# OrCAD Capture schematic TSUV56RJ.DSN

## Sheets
1 02. TSUMV56RJXX: size Custom; title: TSUMV56RJ; rev: V1.0; note: TSUMV56RJ
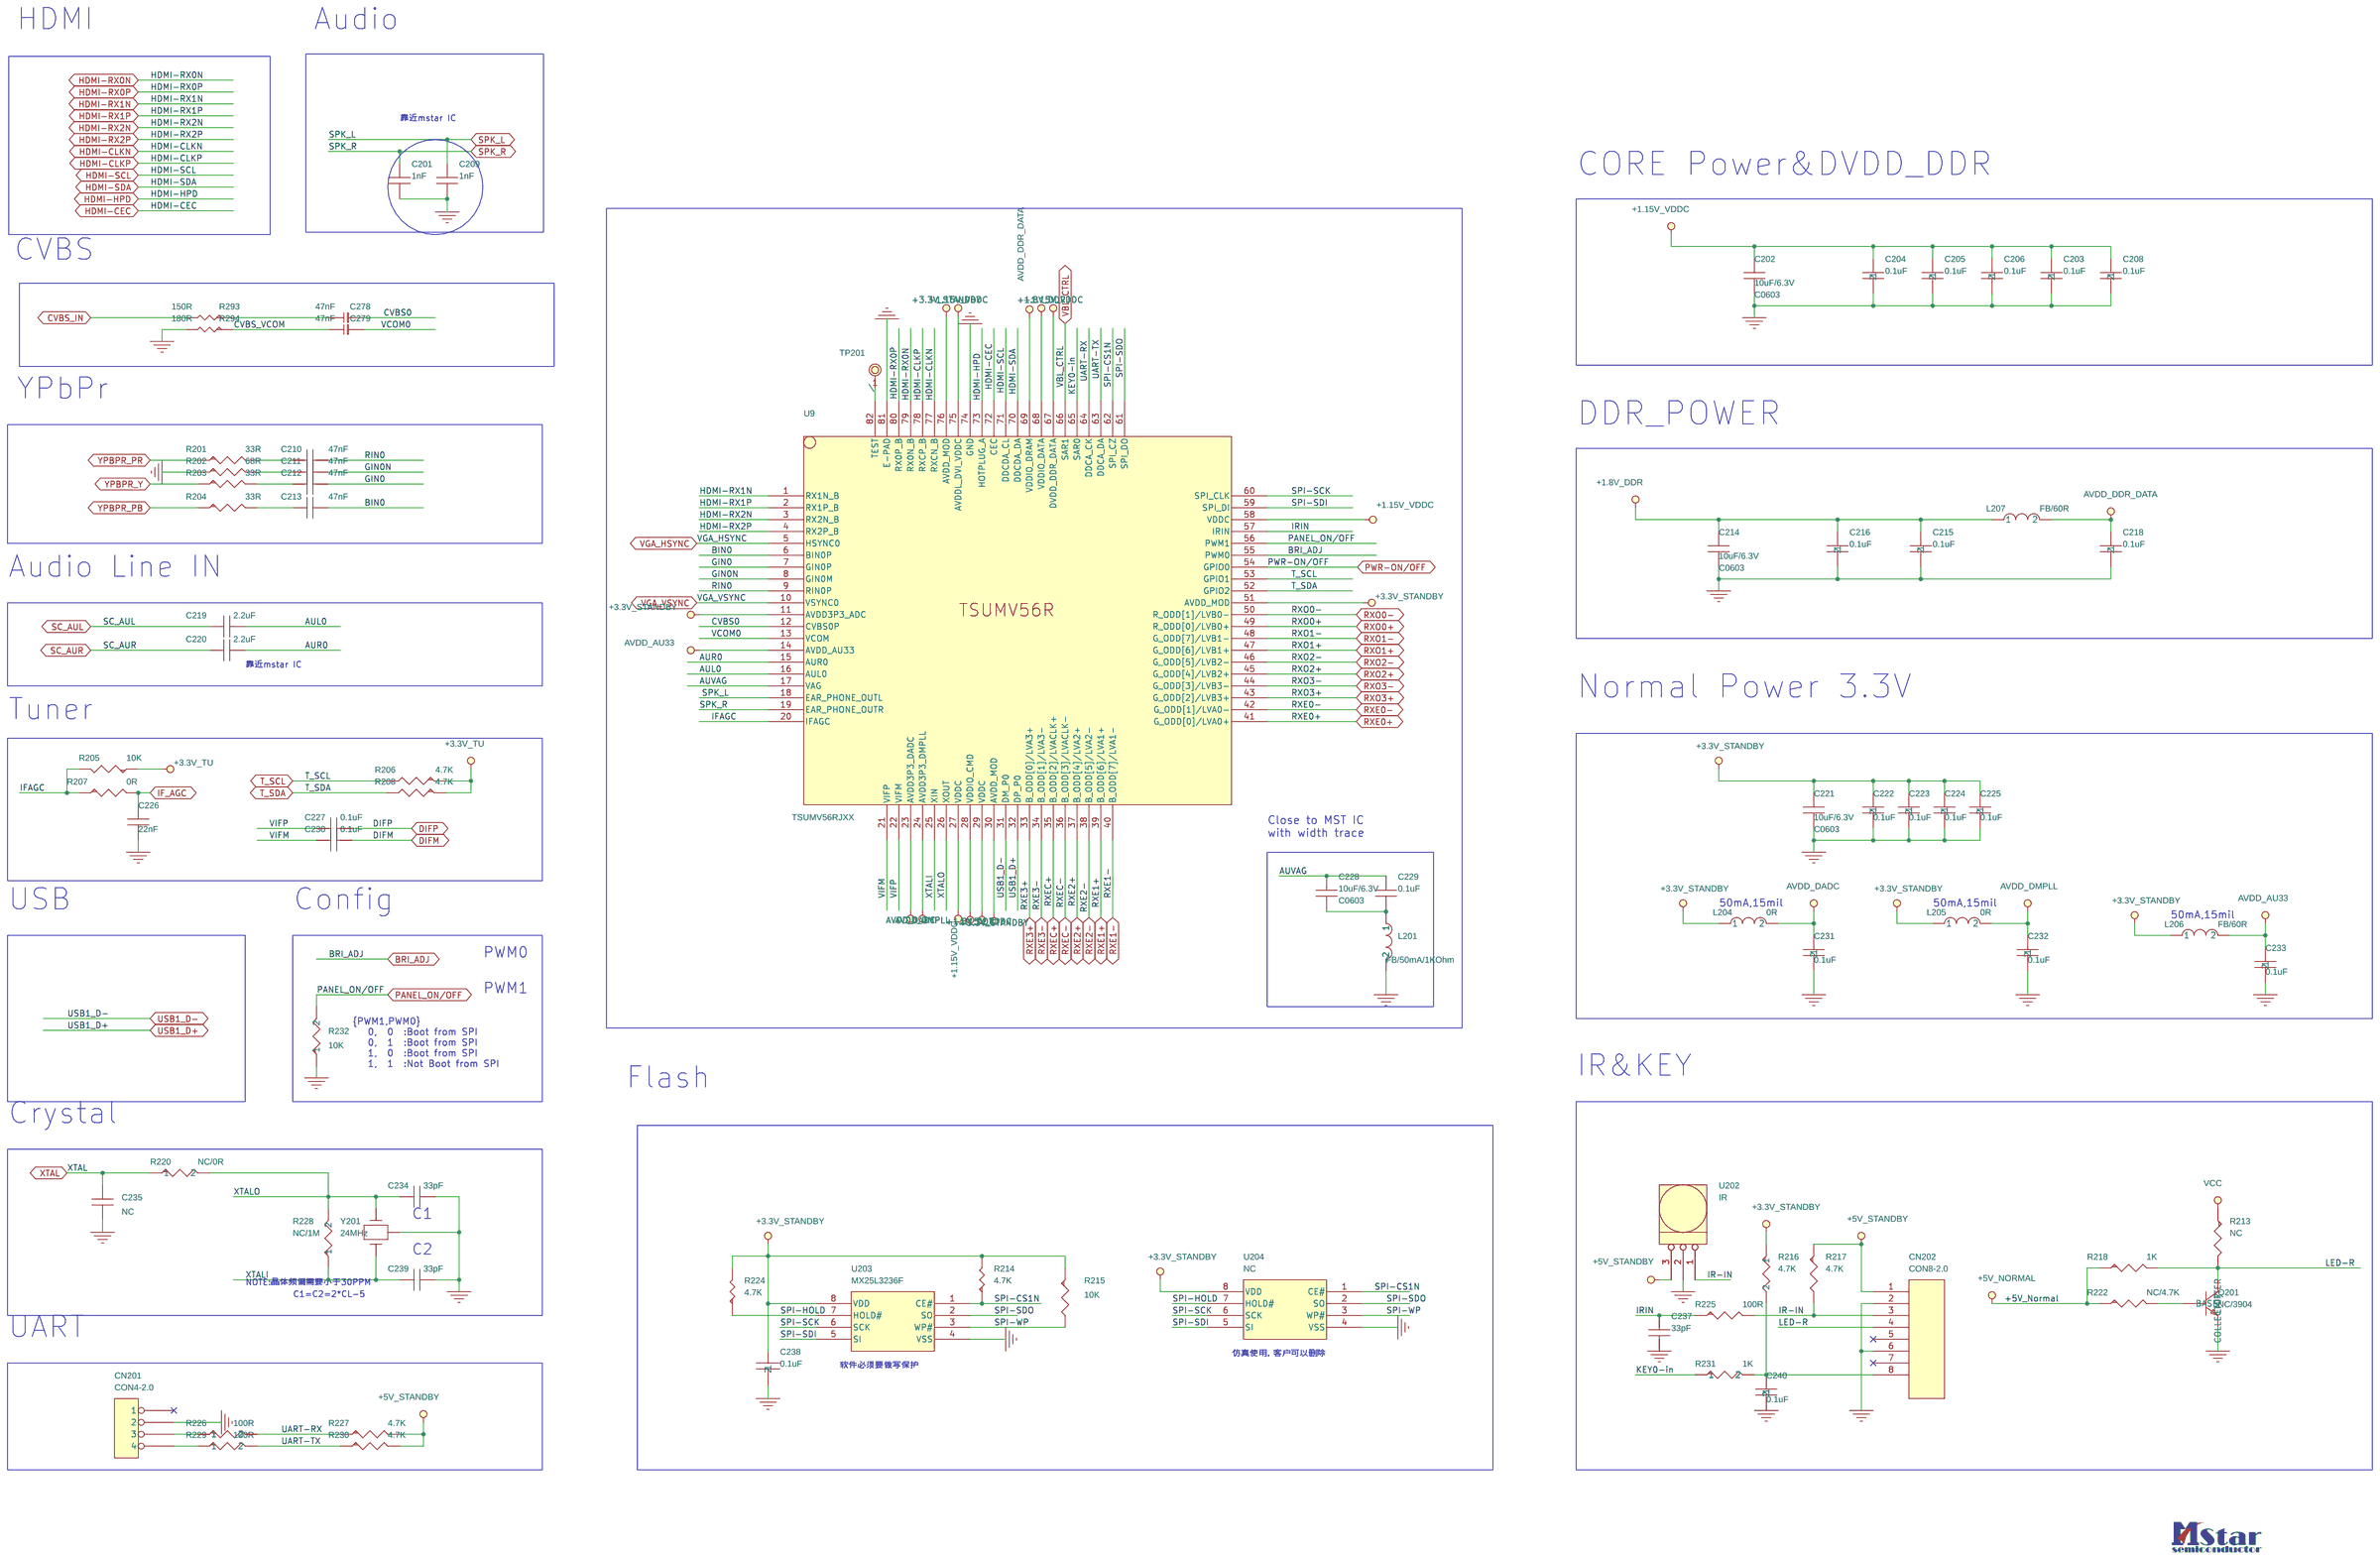
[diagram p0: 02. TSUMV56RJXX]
2 05. Tuner: size Custom; note: Tuner
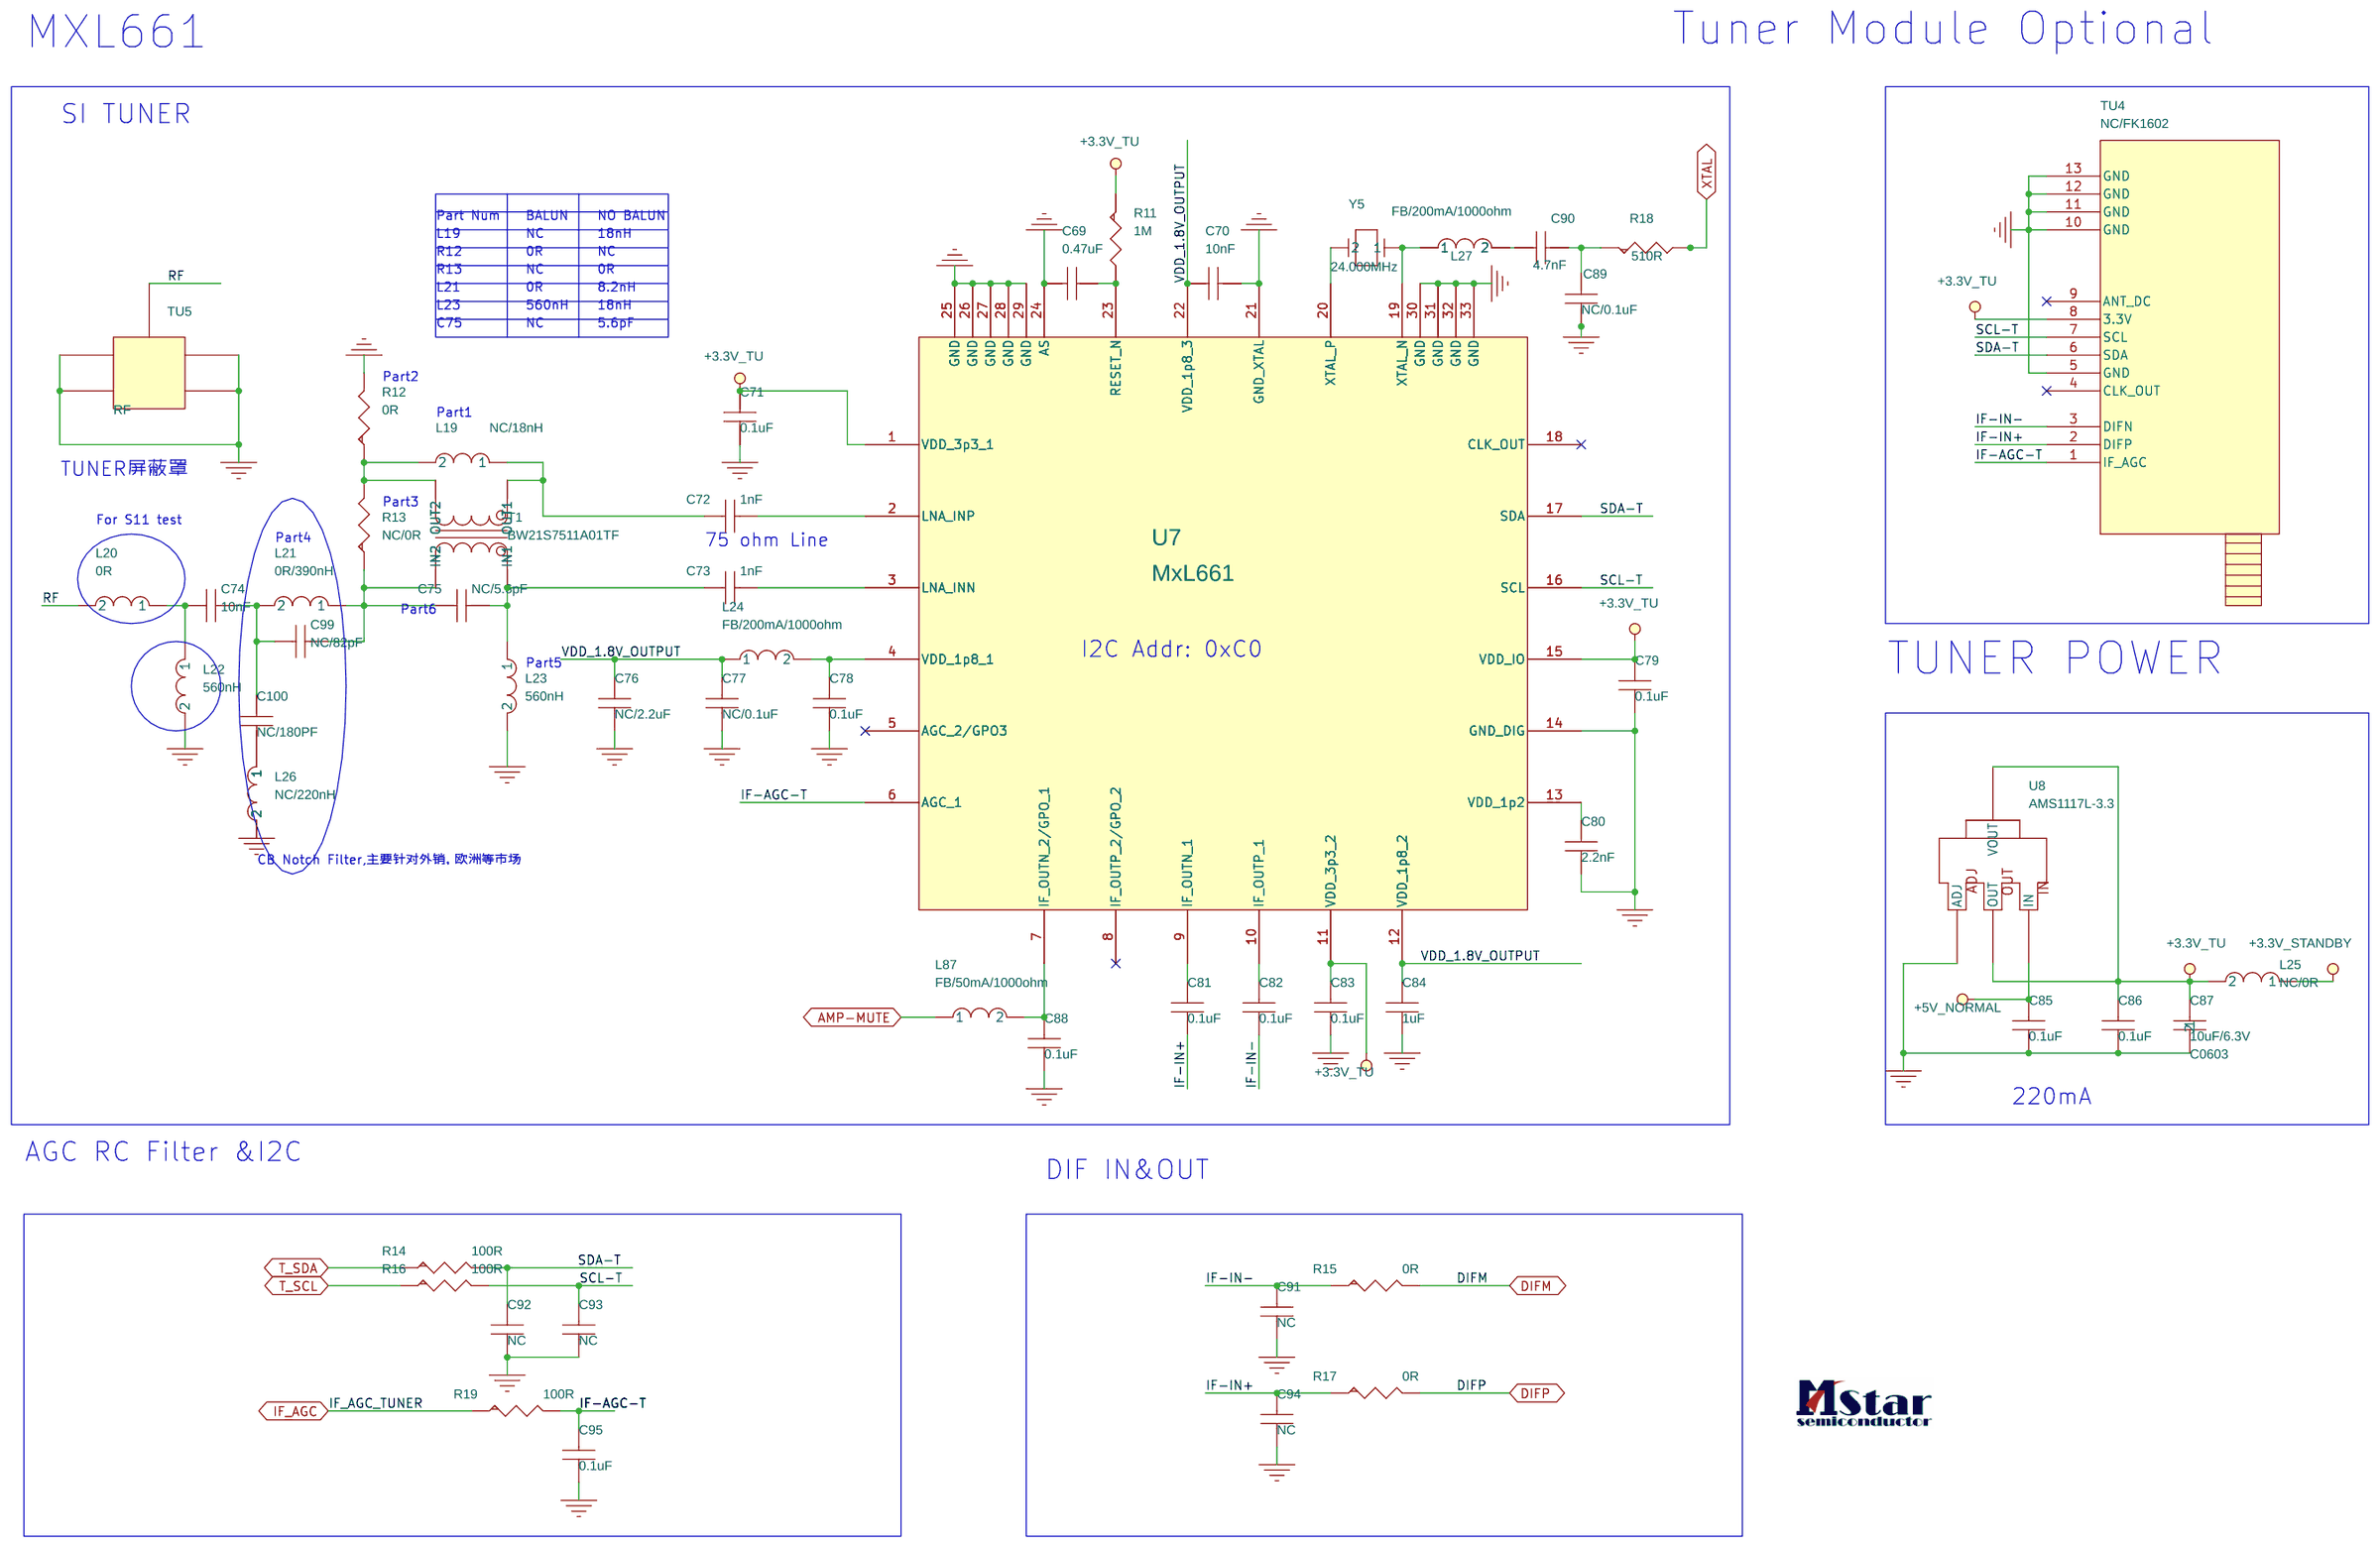
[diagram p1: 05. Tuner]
3 01. System power: size Custom; note: System power
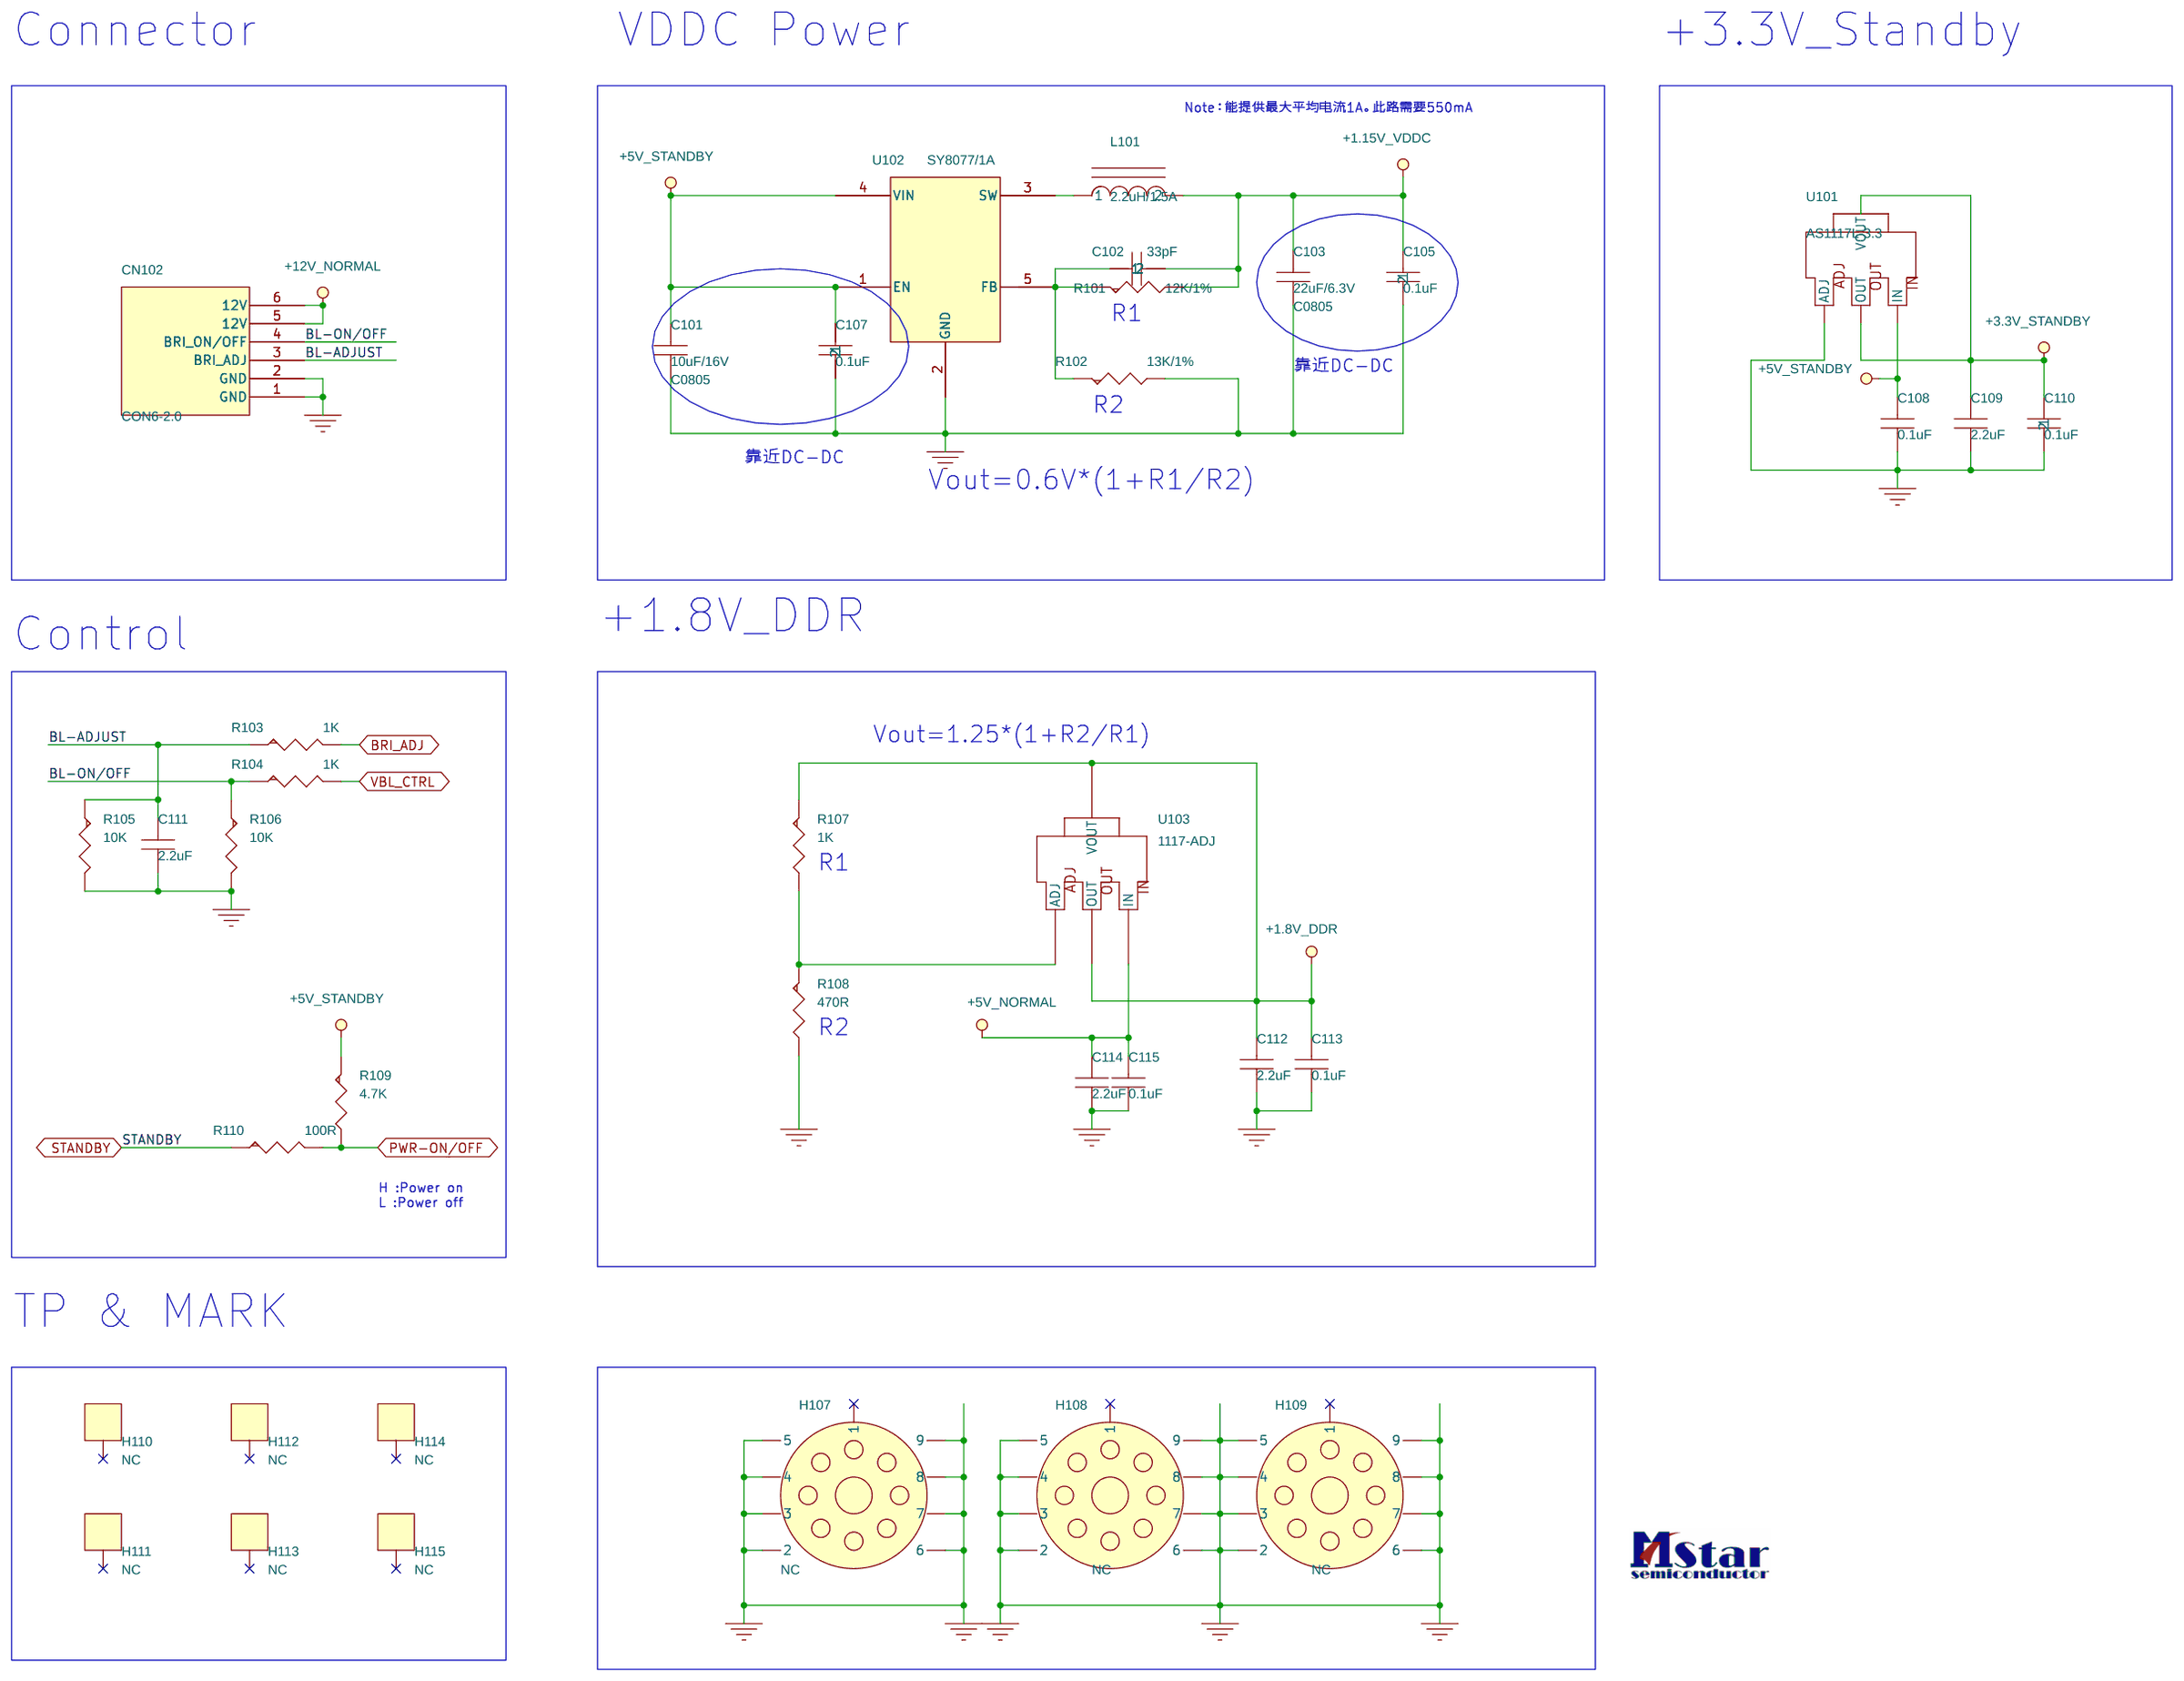
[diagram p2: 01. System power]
4 07. External power board: size Custom; note: External power board
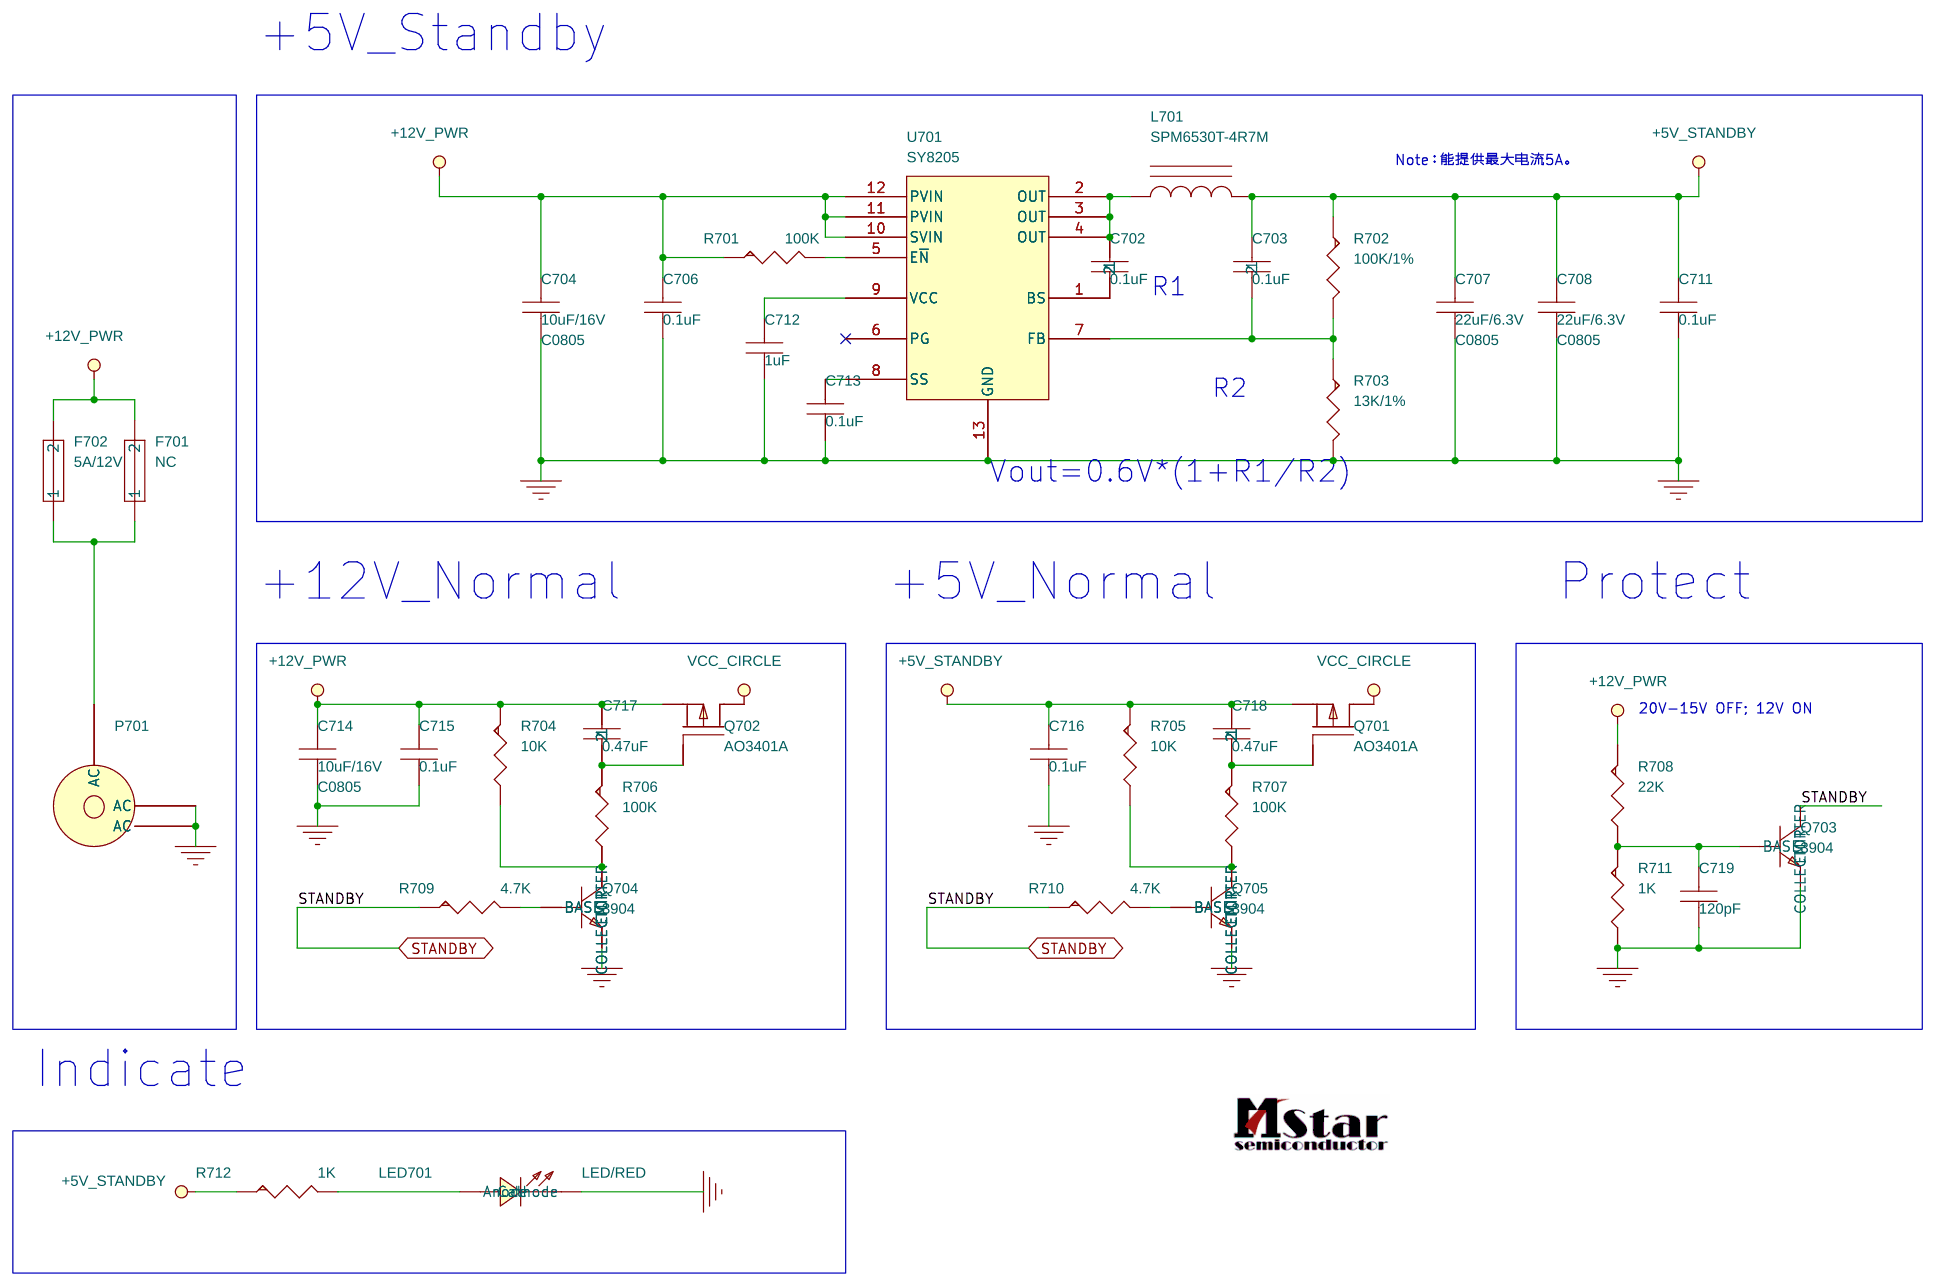
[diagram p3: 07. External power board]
5 06. Amplify: size Custom; note: Audio AMP
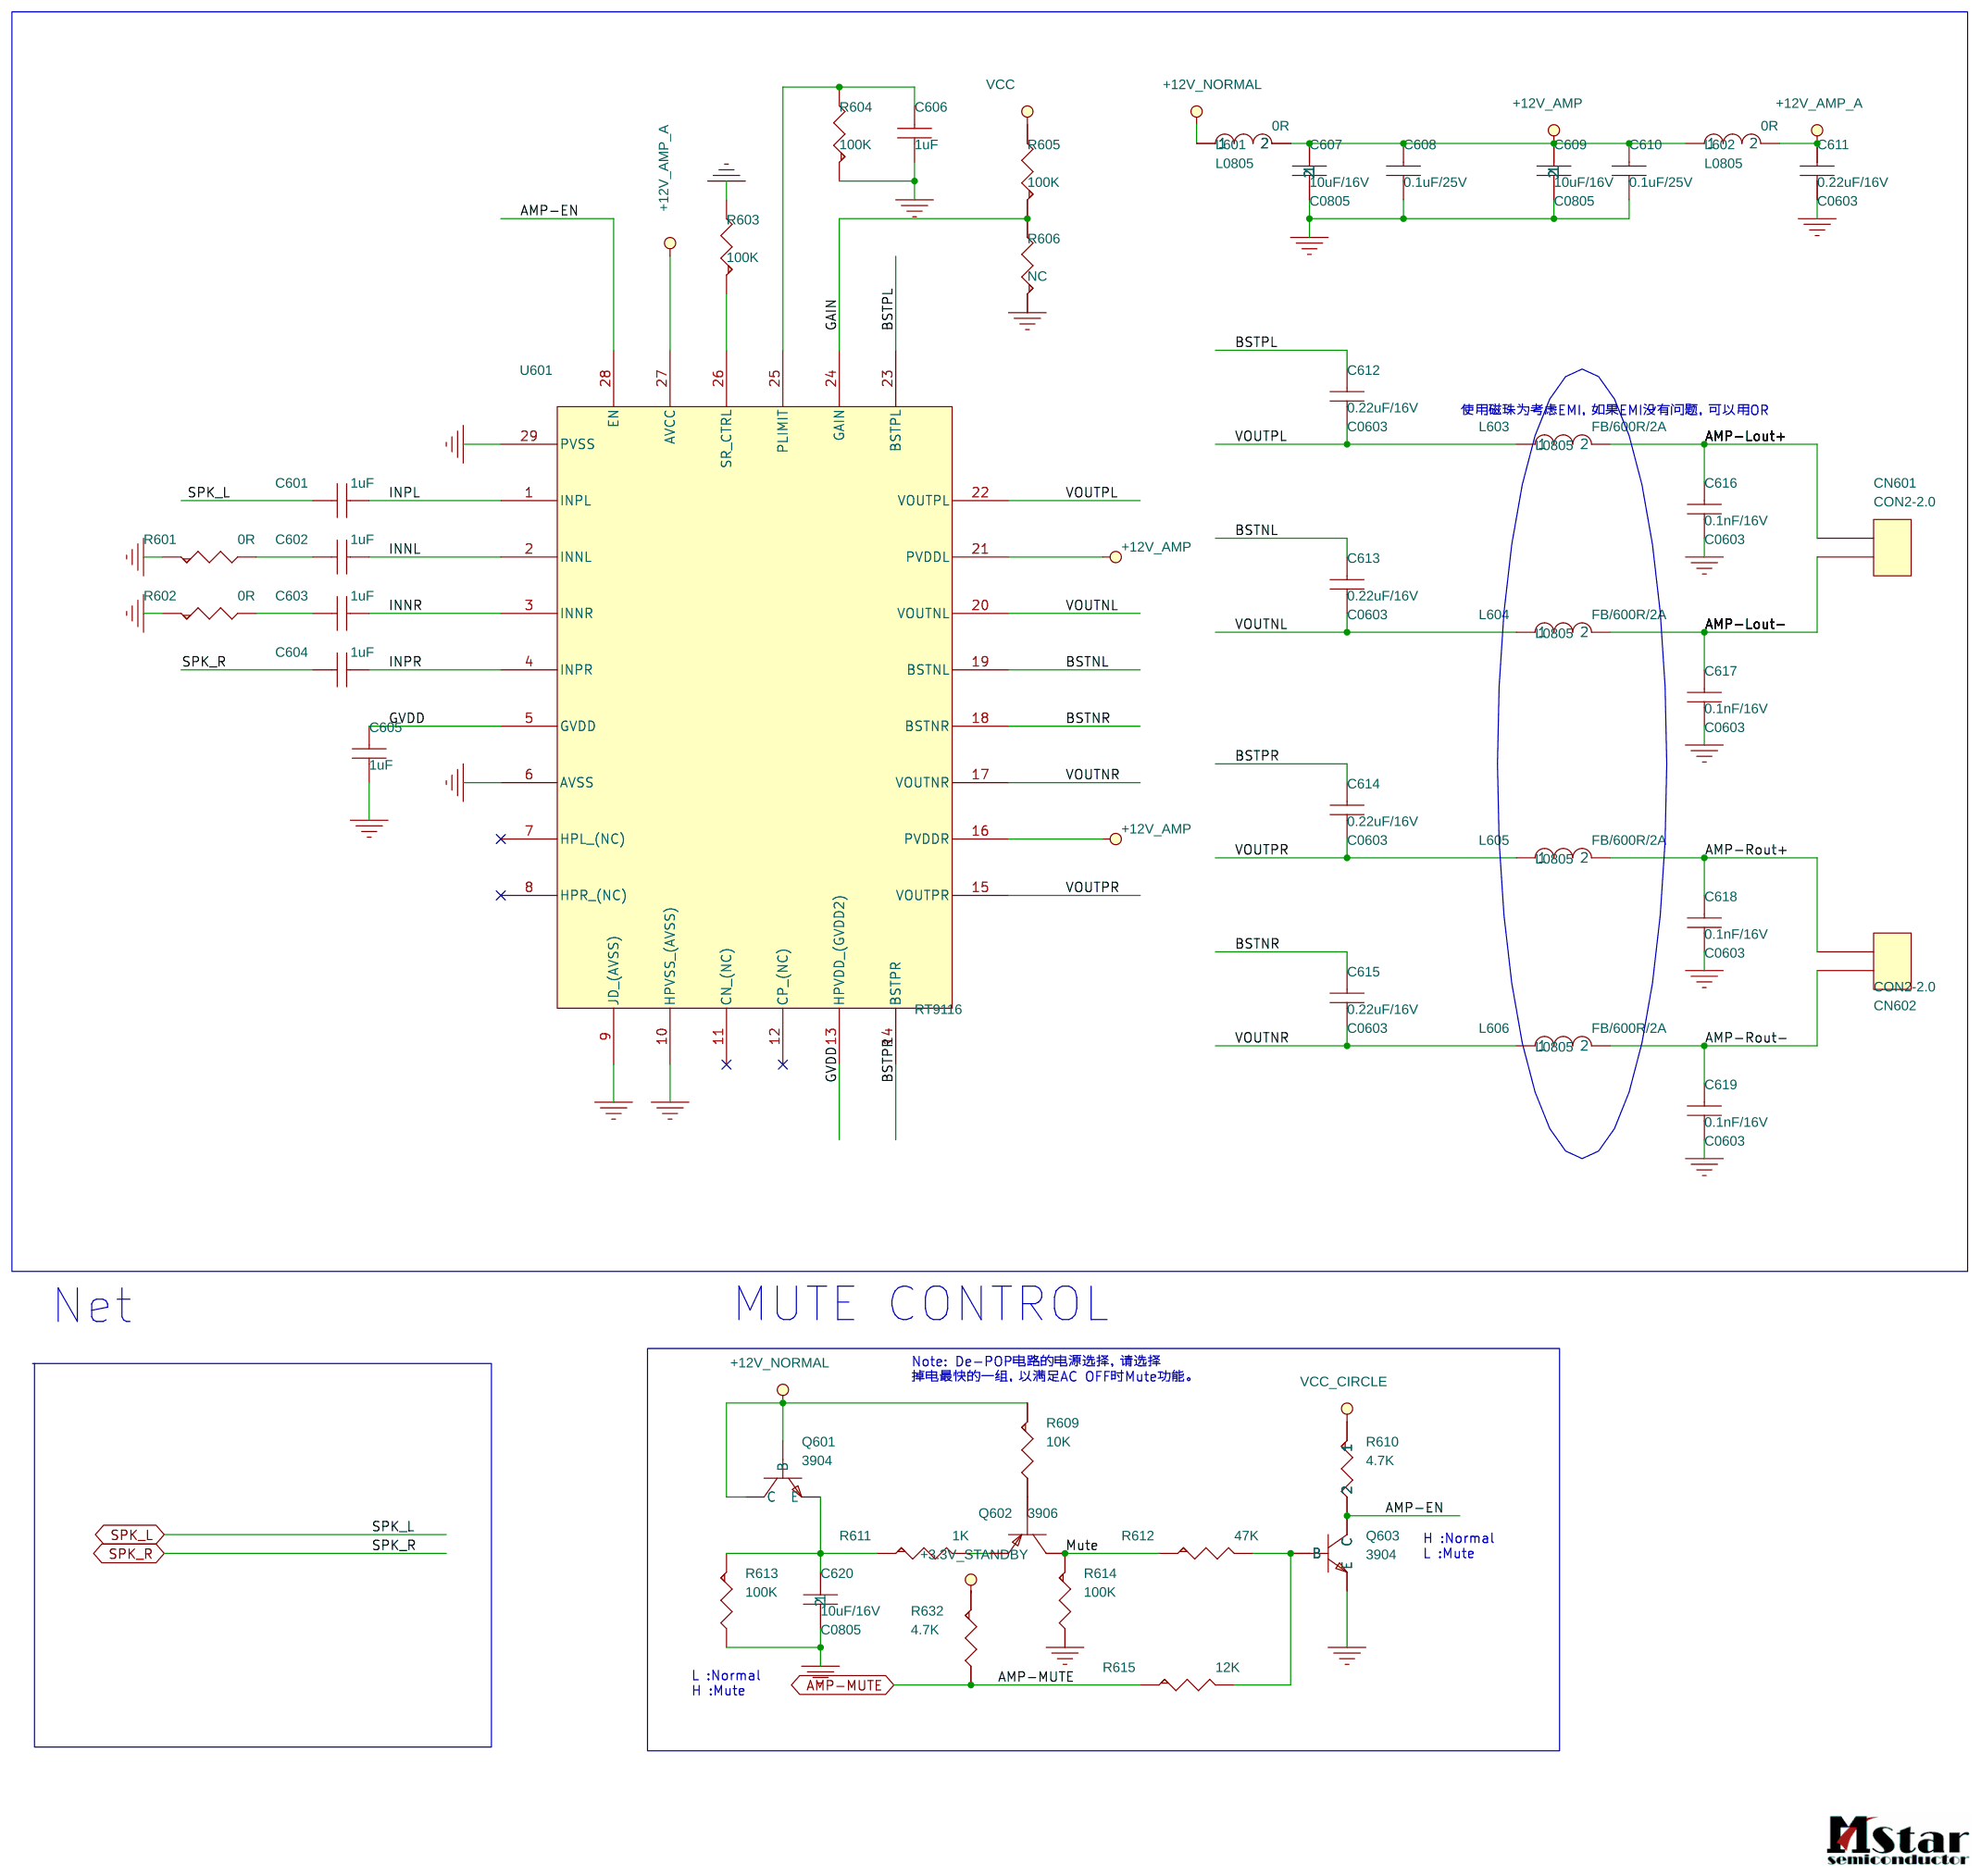
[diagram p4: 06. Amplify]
6 03. LVDS: size Custom; note: LVDS
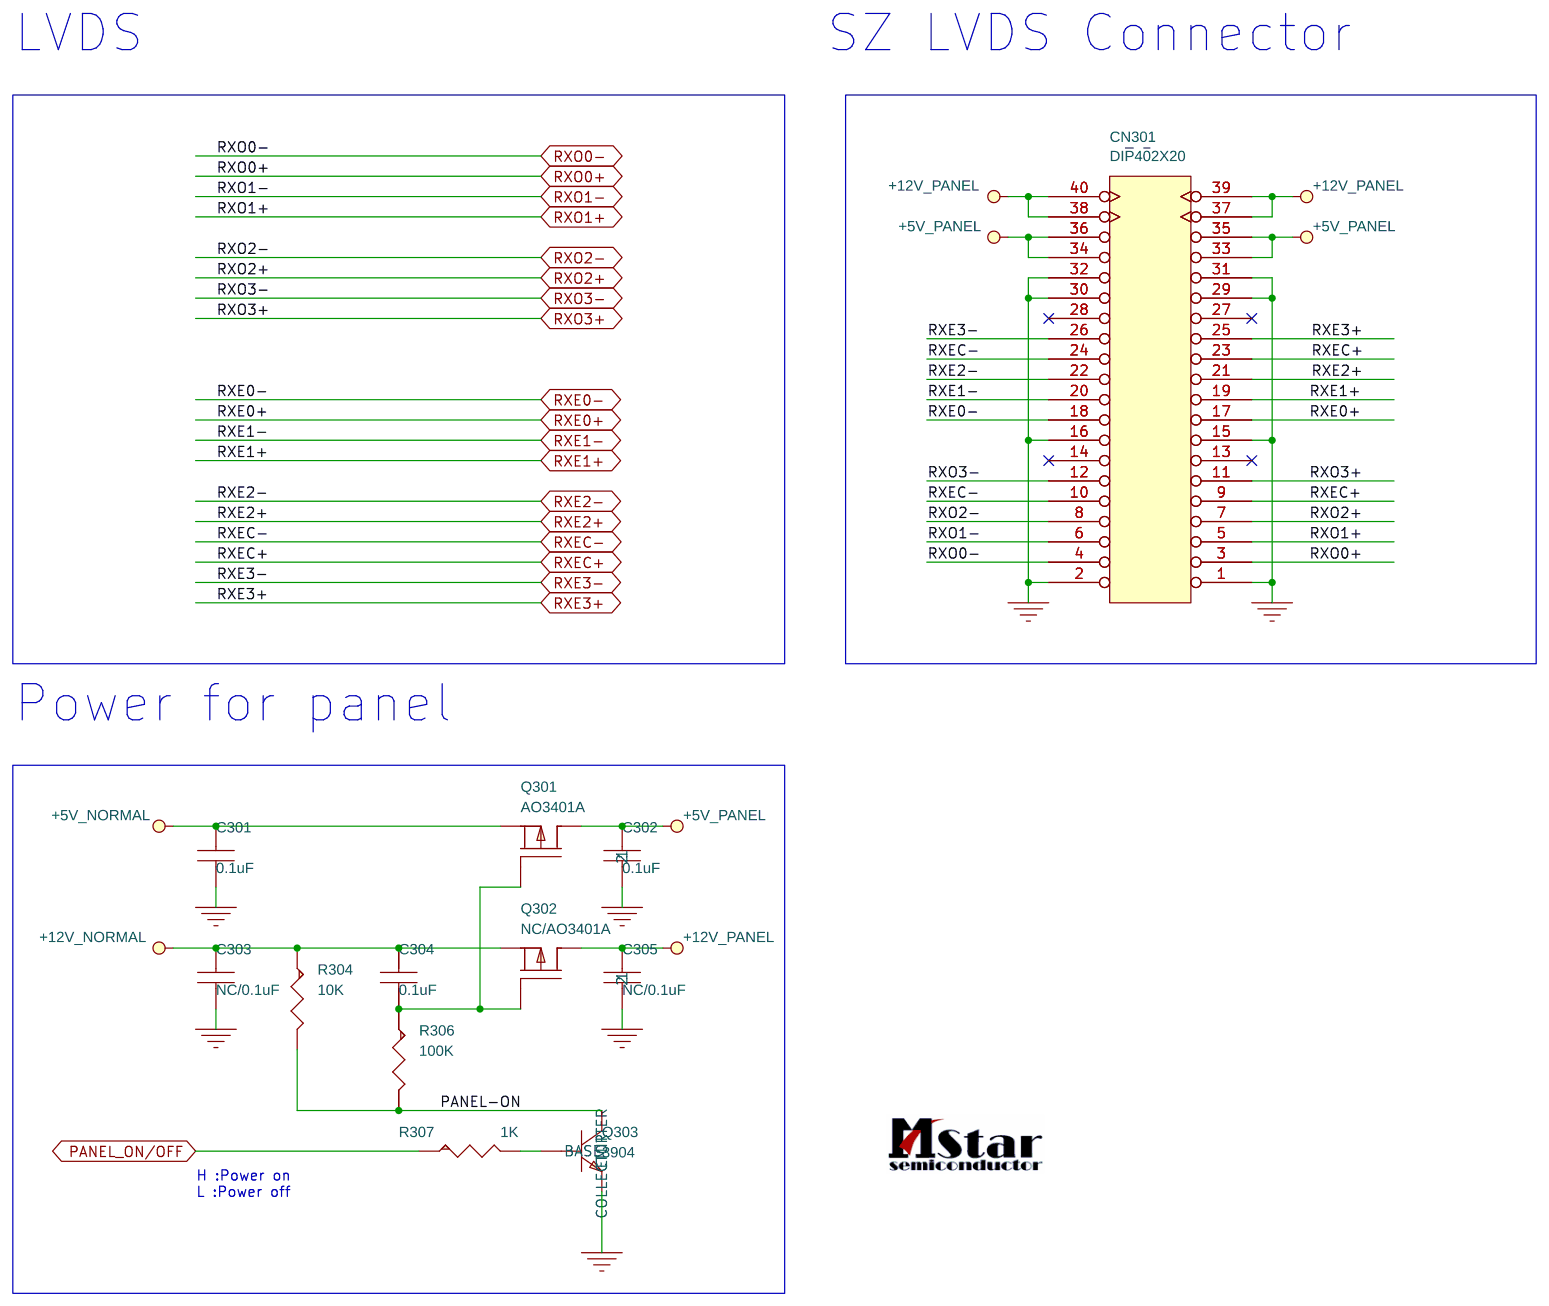
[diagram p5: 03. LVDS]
7 00. Revision: note: Revision History
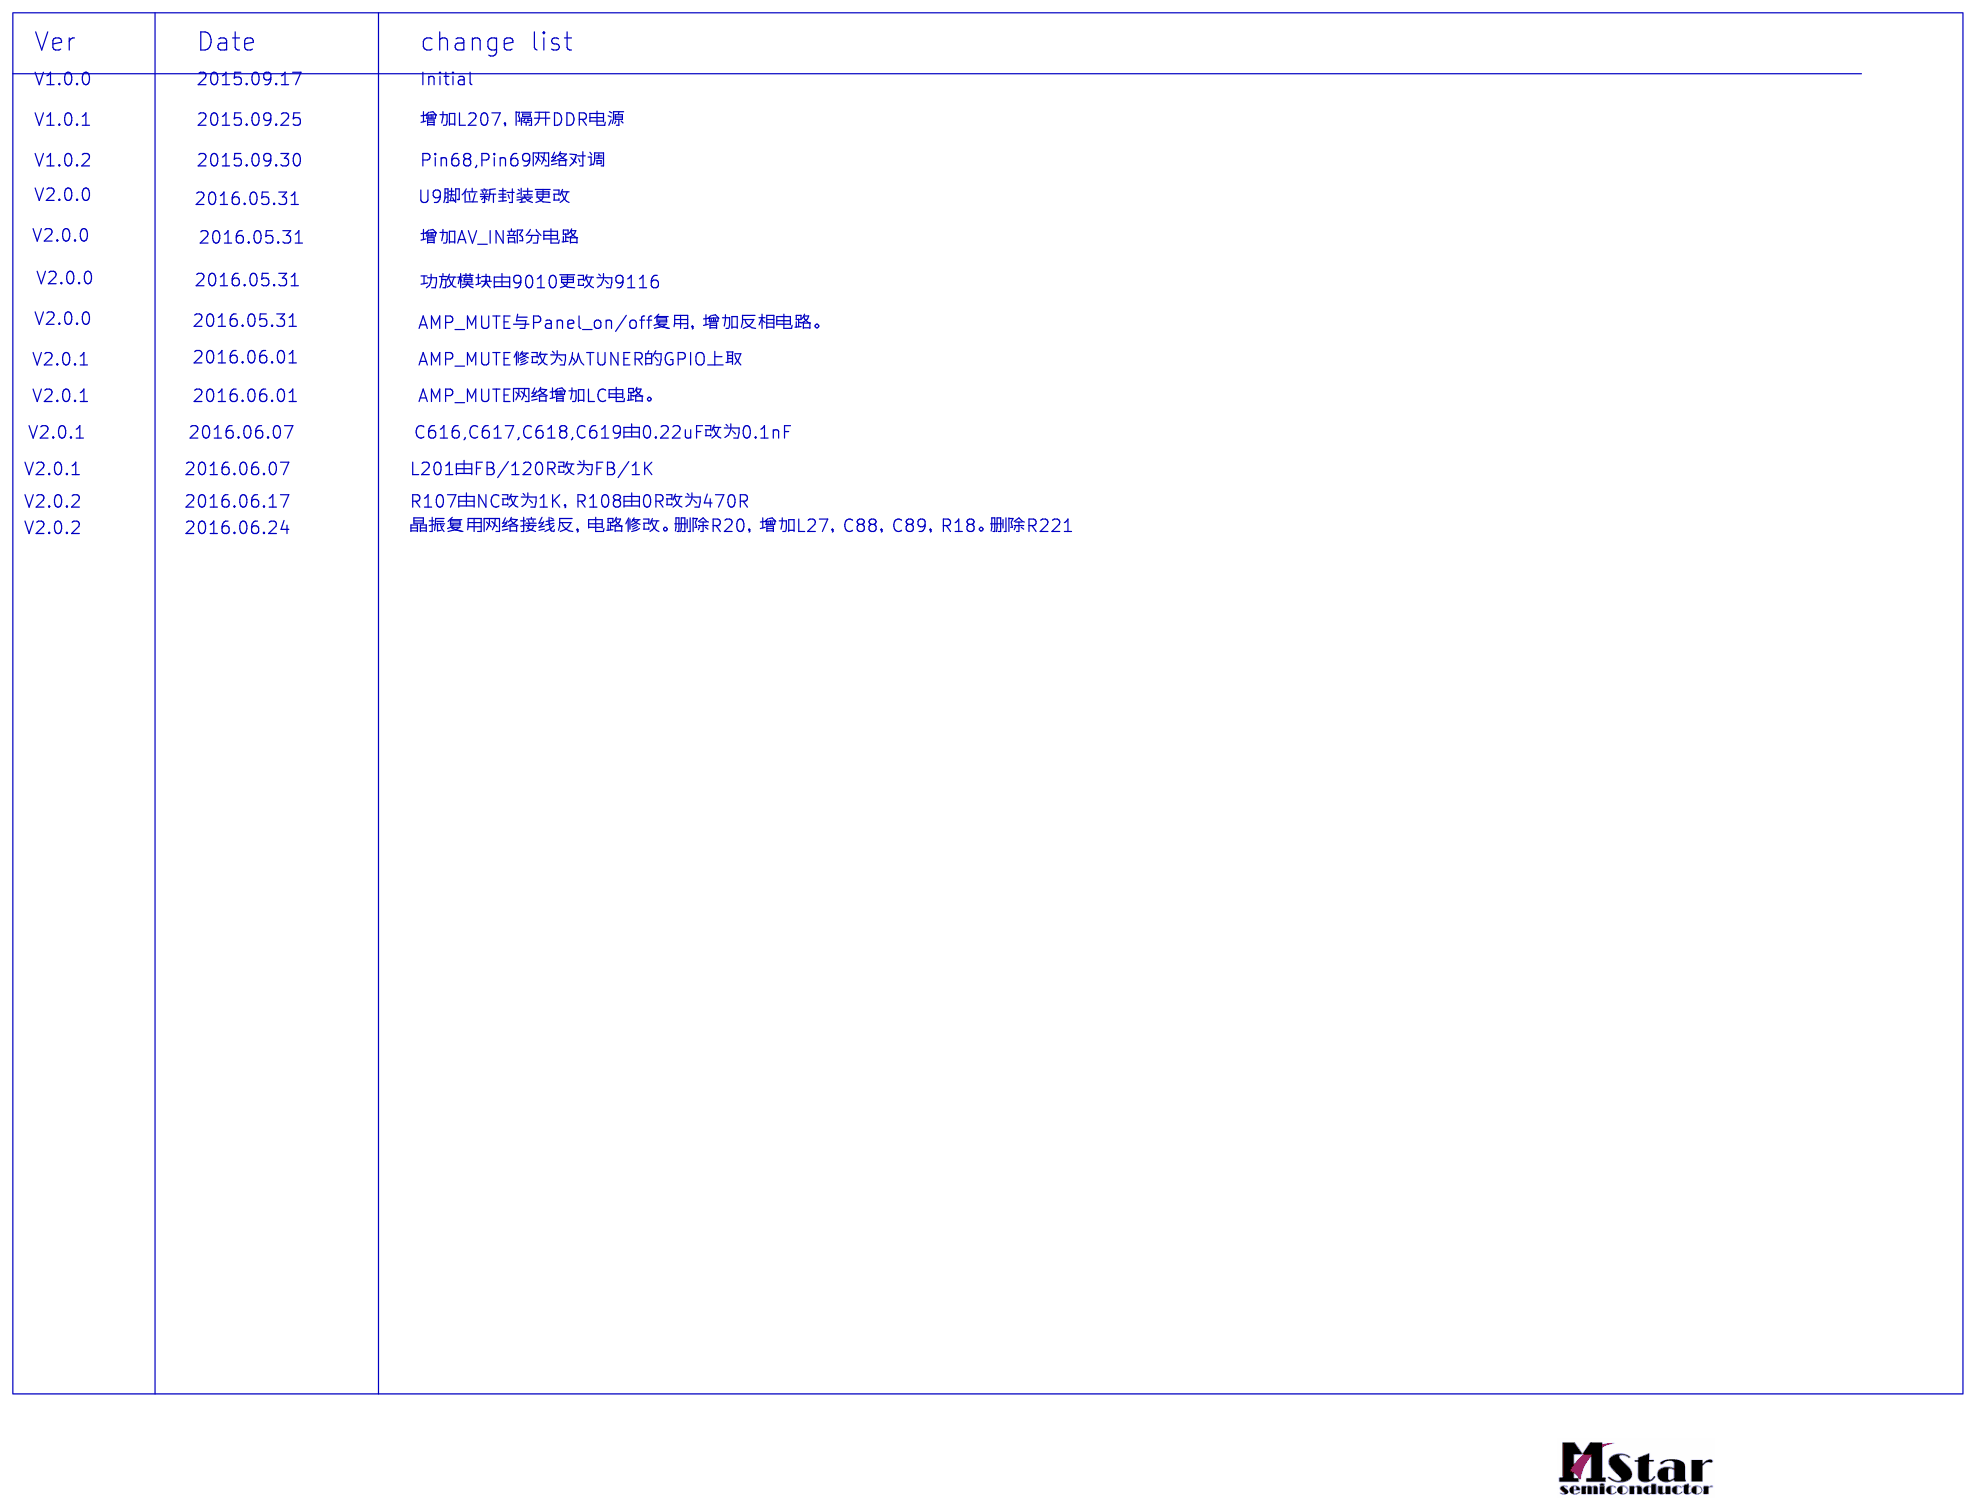
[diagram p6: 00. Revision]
8 04. HDMI/YPbPr/AV/USB: size Custom; note: Video & VGA & USB
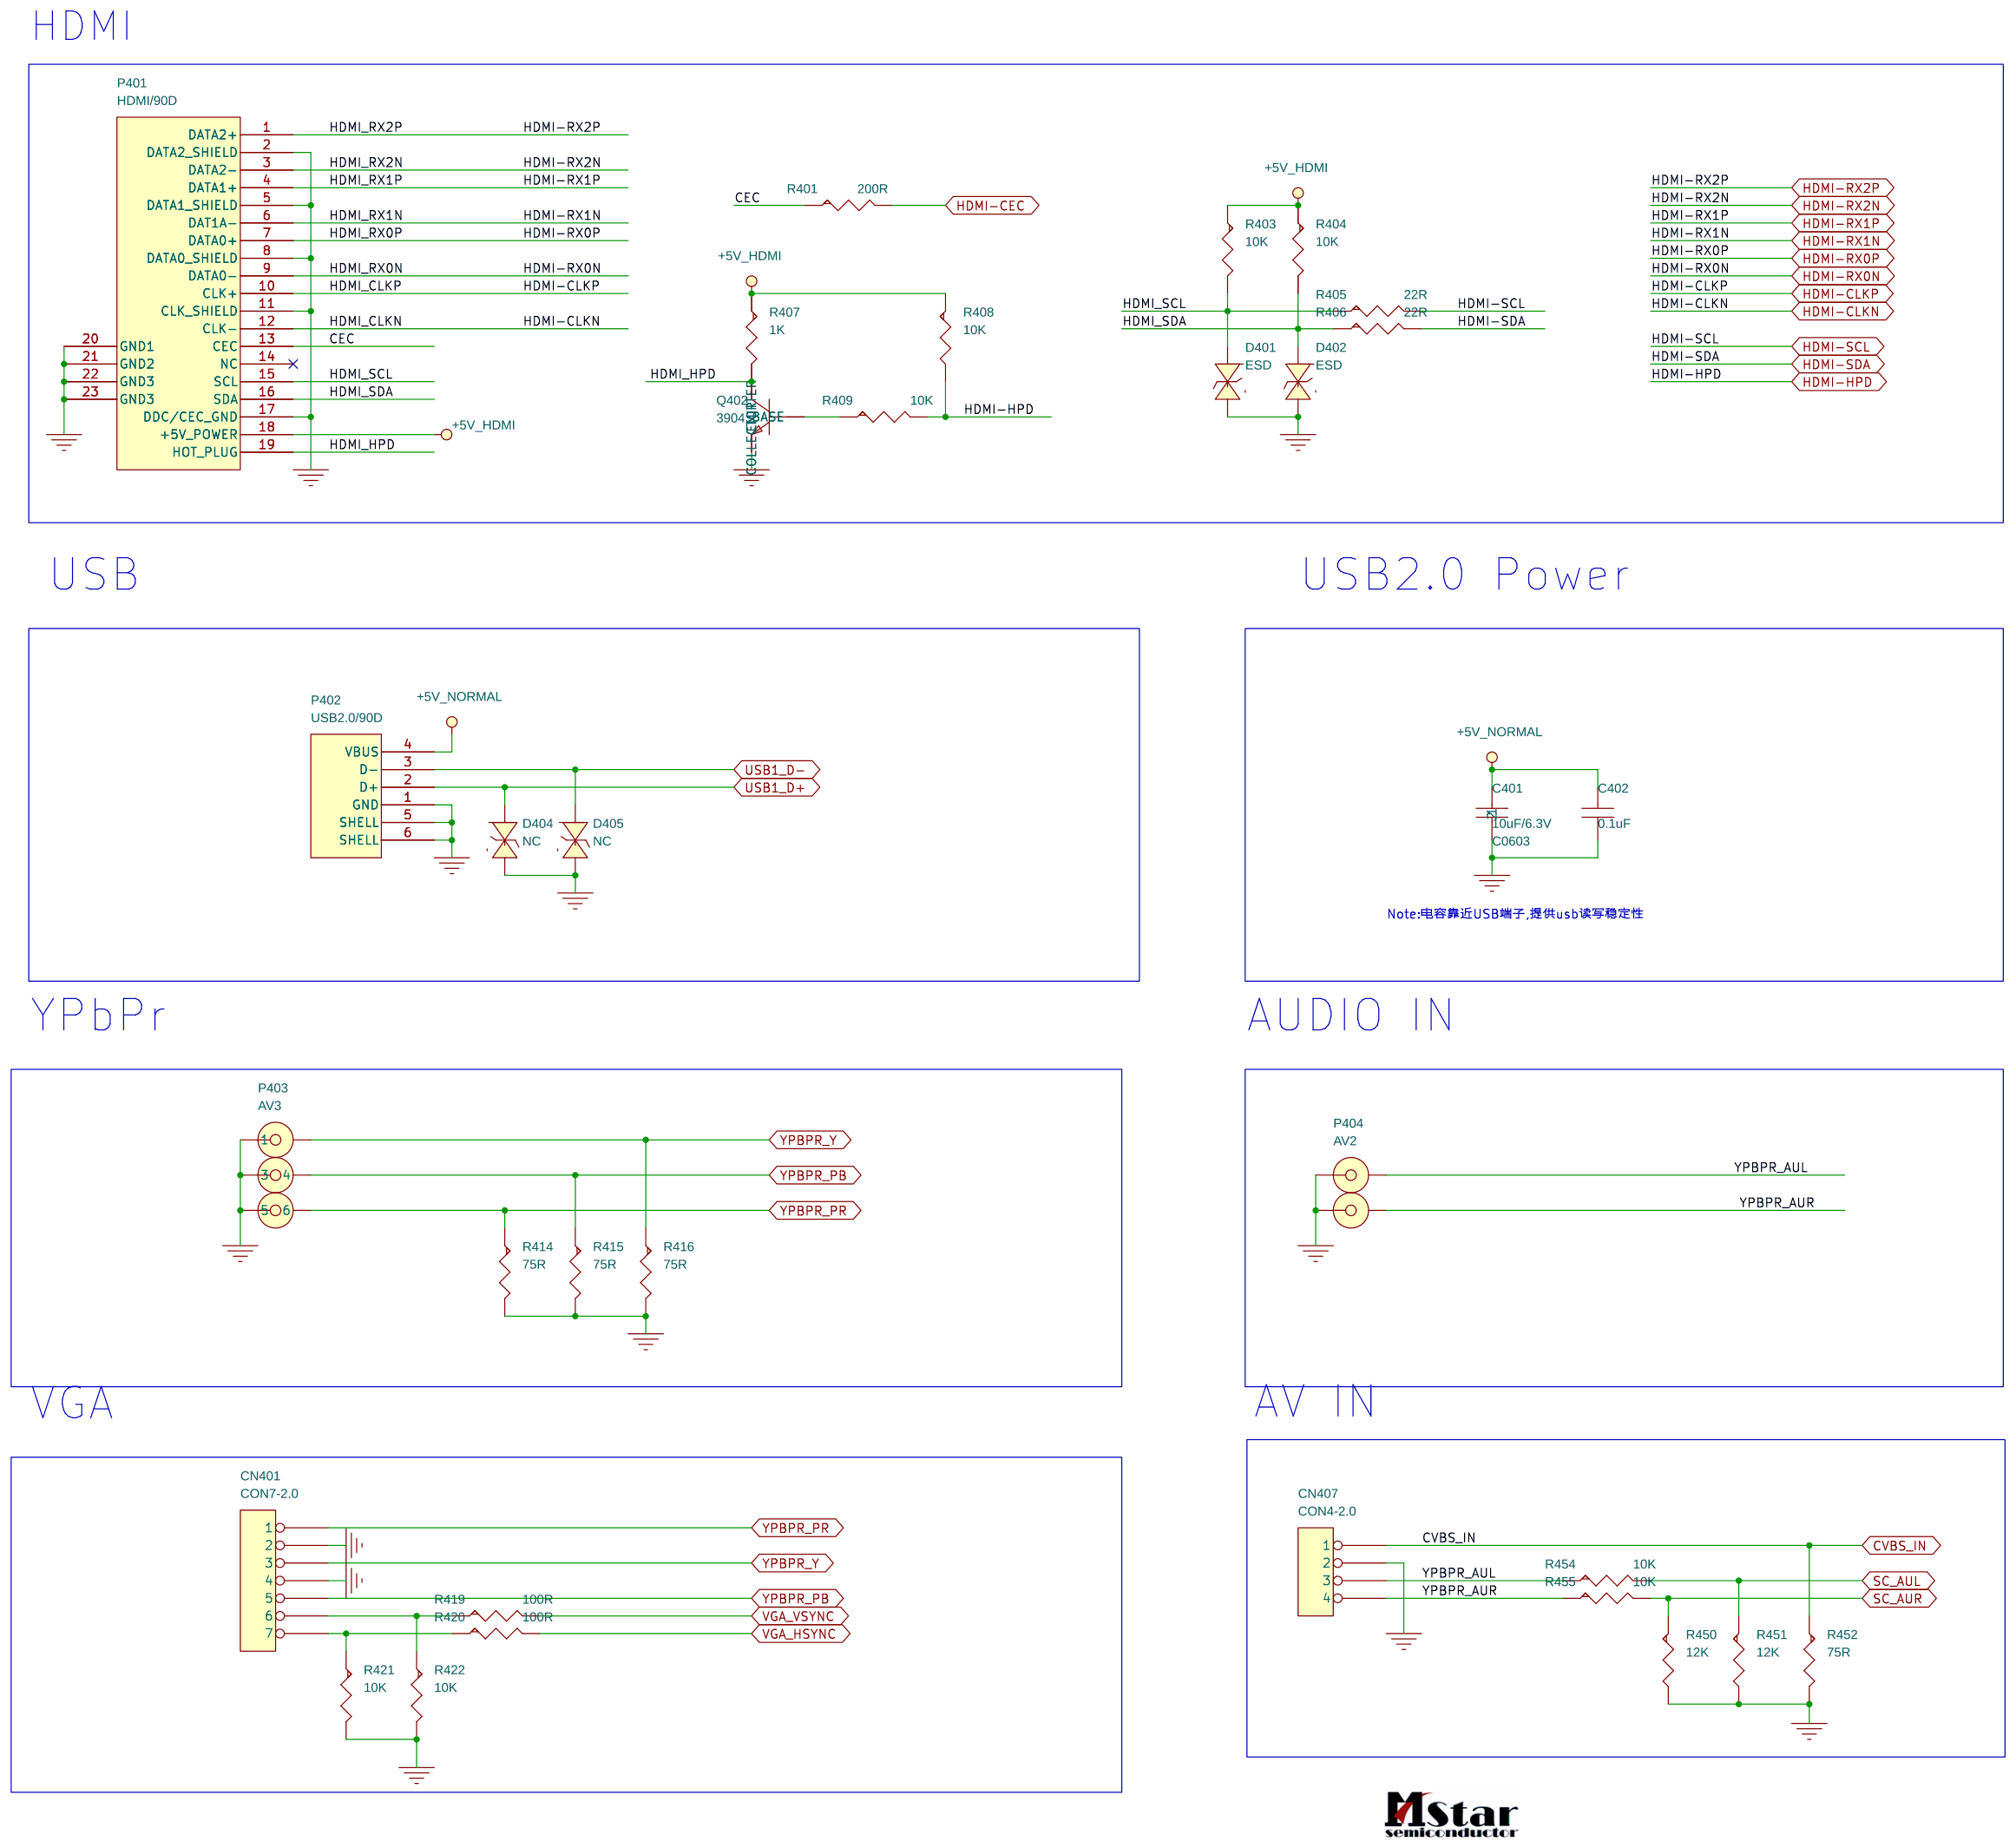
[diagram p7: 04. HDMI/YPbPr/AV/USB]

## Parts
sheet 01. System power
C101  10uF/16V  [C0805]
C102  33pF  [C0402]
C103  22uF/6.3V  [C0805]
C105  0.1uF  [C0402]
C107  0.1uF  [C0402]
C108  0.1uF  [C0603]
C109  2.2uF  [C0603]
C110  0.1uF  [C0402]
C111  2.2uF  [C0603]
C112  2.2uF  [C0603]
C113  0.1uF  [C0402]
C114  2.2uF  [C0603]
C115  0.1uF  [C0402]
CN102  CON6-2.0  [CN6-20A]
H107  NC  [HOLE4-7]
H108  NC  [HOLE4-7]
H109  NC  [HOLE4-7]
H110  NC  [TPAD]
H111  NC  [TPAD]
H112  NC  [TPAD]
H113  NC  [TPAD]
H114  NC  [TPAD]
H115  NC  [TPAD]
L101  2.2uH/1.5A  [SMD03X03]
R101  12K/1%  [R0402]
R102  13K/1%  [R0402]
R103  1K  [R0402]
R104  1K  [R0402]
R105  10K  [R0402]
R106  10K  [R0402]
R107  1K  [R0402]
R108  470R  [R0402]
R109  4.7K  [R0402]
R110  100R  [R0402]
U101  AS1117L-3.3  [SOT-223]
U102  SY8077/1A  [SOT-23-5]
U103  1117-ADJ  [SOT-223]
sheet 02. TSUMV56RJXX
C201  1nF  [C0402]
C202  10uF/6.3V  [C0603]
C203  0.1uF  [C0402]
C204  0.1uF  [C0402]
C205  0.1uF  [C0402]
C206  0.1uF  [C0402]
C208  0.1uF  [C0402]
C209  1nF  [C0402]
C210  47nF  [C0402]
C211  47nF  [C0402]
C212  47nF  [C0402]
C213  47nF  [C0402]
C214  10uF/6.3V  [C0603]
C215  0.1uF  [C0402]
C216  0.1uF  [C0402]
C218  0.1uF  [C0402]
C219  2.2uF  [C0402]
C220  2.2uF  [C0402]
C221  10uF/6.3V  [C0603]
C222  0.1uF  [C0402]
C223  0.1uF  [C0402]
C224  0.1uF  [C0402]
C225  0.1uF  [C0402]
C226  22nF  [C0402]
C227  0.1uF  [C0402]
C228  10uF/6.3V  [C0603]
C229  0.1uF  [C0402]
C230  0.1uF  [C0402]
C231  0.1uF  [C0402]
C232  0.1uF  [C0402]
C233  0.1uF  [C0402]
C234  33pF  [C0402]
C235  NC  [C0402]
C237  33pF  [C0402]
C238  0.1uF  [C0402]
C239  33pF  [C0402]
C240  0.1uF  [C0402]
C278  47nF  [C0402]
C279  47nF  [C0402]
CN201  CON4-2.0  [CN4-20A]
CN202  CON8-2.0  [CN8-20A]
L201  FB/50mA/1KOhm  [L0402]
L204  0R  [L0402]
L205  0R  [L0402]
L206  FB/60R  [L0402]
L207  FB/60R  [L0402]
Q201  NC/3904  [SOT-23]
R201  33R  [R0402]
R202  68R  [R0402]
R203  33R  [R0402]
R204  33R  [R0402]
R205  10K  [R0402]
R206  4.7K  [R0402]
R207  0R  [R0402]
R208  4.7K  [R0402]
R213  NC  [R0402]
R214  4.7K  [R0402]
R215  10K  [R0402]
R216  4.7K  [R0402]
R217  4.7K  [R0402]
R218  1K  [R0402]
R220  NC/0R  [R0402]
R222  NC/4.7K  [R0402]
R224  4.7K  [R0402]
R225  100R  [R0402]
R226  100R  [R0402]
R227  4.7K  [R0402]
R228  NC/1M  [R0402]
R229  100R  [R0402]
R230  4.7K  [R0402]
R231  1K  [R0402]
R232  10K  [R0402]
R293  150R  [R0402]
R294  180R  [R0402]
TP201  NC  [TP-0.5mm]
U9  TSUMV56RJXX  [IC-80P-LQFP-10X10-P04]
U202  IR  [IR-1]
U203  MX25L3236F  [SOP8-255-50]
U204  NC  [SOP8-255-50]
Y201  24MHz  [XTAL\HC49\F]
sheet 03. LVDS
C301  0.1uF  [C0603]
C302  0.1uF  [C0402]
C303  NC/0.1uF  [C0603]
C304  0.1uF  [C0603]
C305  NC/0.1uF  [C0402]
CN301  DIP\40\2X20  [CON20X2-2.0-LVDS]
Q301  AO3401A  [SOT23-100]
Q302  NC/AO3401A  [SOT23-100]
Q303  3904  [SOT-23]
R304  10K  [R0402]
R306  100K  [R0402]
R307  1K  [R0402]
sheet 04. HDMI/YPbPr/AV/USB
C401  10uF/6.3V
C402  0.1uF  [C0402]
CN401  CON7-2.0  [CN7-20A]
CN407  CON4-2.0  [CN4-20A]
D401  ESD  [D0402]
D402  ESD  [D0402]
D404  NC  [D0402]
D405  NC  [D0402]
P401  HDMI/90D  [HDMI_TYPE_A]
P402  USB2.0/90D  [USB_MINI_4P]
P403  AV3  [RCV3-14MM-1]
P404  AV2  [RCV2-14MM-1]
Q402  3904  [SOT-23]
R401  200R  [R0402]
R403  10K  [R0402]
R404  10K  [R0402]
R405  22R  [R0402]
R406  22R  [R0402]
R407  1K  [R0402]
R408  10K  [R0402]
R409  10K  [R0402]
R414  75R  [R0402]
R415  75R  [R0402]
R416  75R  [R0402]
R419  100R  [R0402]
R420  100R  [R0402]
R421  10K  [R0402]
R422  10K  [R0402]
R450  12K  [R0402]
R451  12K  [R0402]
R452  75R  [R0402]
R454  10K  [R0402]
R455  10K  [R0402]
sheet 05. Tuner
C69  0.47uF  [C0402]
C70  10nF  [C0402]
C71  0.1uF  [C0402]
C72  1nF  [C0402]
C73  1nF  [C0402]
C74  10nF  [C0402]
C75  NC/5.6pF  [C0402]
C76  NC/2.2uF  [C0402]
C77  NC/0.1uF  [C0402]
C78  0.1uF  [C0402]
C79  0.1uF  [C0402]
C80  2.2nF  [C0402]
C81  0.1uF  [C0402]
C82  0.1uF  [C0402]
C83  0.1uF  [C0402]
C84  1uF  [C0402]
C85  0.1uF  [C0603]
C86  0.1uF  [C0603]
C87  10uF/6.3V  [C0603]
C88  0.1uF  [C0402]
C89  NC/0.1uF  [C0402]
C90  4.7nF  [C0402]
C91  NC  [C0603]
C92  NC  [C0402]
C93  NC  [C0402]
C94  NC  [C0603]
C95  0.1uF  [C0402]
C99  NC/82pF  [C0402]
C100  NC/180PF  [C0402]
L19  NC/18nH  [L0402]
L20  0R  [L0402]
L21  0R/390nH  [L0402]
L22  560nH  [L0402]
L23  560nH  [L0402]
L24  FB/200mA/1000ohm  [L0402]
L25  NC/0R  [L0805]
L26  NC/220nH  [L0402]
L27  FB/200mA/1000ohm  [L0402]
L87  FB/50mA/1000ohm  [L0402]
R11  1M  [R0402]
R12  0R  [R0402]
R13  NC/0R  [R0402]
R14  100R  [R0402]
R15  0R  [R0402]
R16  100R  [R0402]
R17  0R  [R0402]
R18  510R  [R0402]
R19  100R  [R0402]
T1  BW21S7511A01TF  [trans_atb2012]
TU4  NC/FK1602  [FK1602]
TU5  RF  [TUNER-C2]
U7  MxL661  [QFN24_MXL601]
U8  AMS1117L-3.3  [SOT-223]
Y5  24.000MHz  [XTAL\HC49\F]
sheet 06. Amplify
C601  1uF  [C0402]
C602  1uF  [C0402]
C603  1uF  [C0402]
C604  1uF  [C0402]
C605  1uF  [C0402]
C606  1uF  [C0402]
C607  10uF/16V
C608  0.1uF/25V  [C0402]
C609  10uF/16V
C610  0.1uF/25V  [C0402]
C611  0.22uF/16V  [C0603]
C612  0.22uF/16V  [C0603]
C613  0.22uF/16V  [C0603]
C614  0.22uF/16V  [C0603]
C615  0.22uF/16V  [C0603]
C616  0.1nF/16V  [C0603]
C617  0.1nF/16V  [C0603]
C618  0.1nF/16V  [C0603]
C619  0.1nF/16V  [C0603]
C620  10uF/16V
CN601  CON2-2.0  [CN2-20A]
CN602  CON2-2.0  [CN2-20A]
L601  0R  [L0805]
L602  0R  [L0805]
L603  FB/600R/2A  [L0805]
L604  FB/600R/2A  [L0805]
L605  FB/600R/2A  [L0805]
L606  FB/600R/2A  [L0805]
Q601  3904  [SOT-23]
Q602  3906  [SOT-23]
Q603  3904  [SOT-23]
R601  0R  [R0402]
R602  0R  [R0402]
R603  100K  [R0402]
R604  100K  [R0402]
R605  100K  [R0402]
R606  NC  [R0402]
R609  10K  [R0402]
R610  4.7K  [R0402]
R611  1K  [R0402]
R612  47K  [R0402]
R613  100K  [R0402]
R614  100K  [R0402]
R615  12K  [R0402]
R632  4.7K  [R0402]
U601  RT9116  [QFN4X5_28L_0-5_3]
sheet 07. External power board
C702  0.1uF  [C0402]
C703  0.1uF  [C0402]
C704  10uF/16V  [C0805]
C706  0.1uF  [C0402]
C707  22uF/6.3V  [C0805]
C708  22uF/6.3V  [C0805]
C711  0.1uF  [C0402]
C712  1uF  [C0402]
C713  0.1uF  [C0402]
C714  10uF/16V  [C0805]
C715  0.1uF  [C0402]
C716  0.1uF  [C0402]
C717  0.47uF  [C0603]
C718  0.47uF  [C0603]
C719  120pF  [C0402]
F701  NC  [R1206]
F702  5A/12V  [AXIAL0.4]
L701  SPM6530T-4R7M  [SMD08X08]
LED701  LED/RED  [LED]
P701  DCJACK  [DC-JACK3P]
Q701  AO3401A  [SOT23-100]
Q702  AO3401A  [SOT23-100]
Q703  3904  [SOT-23]
Q704  3904  [SOT-23]
Q705  3904  [SOT-23]
R701  100K  [R0402]
R702  100K/1%  [R0402]
R703  13K/1%  [R0402]
R704  10K  [R0402]
R705  10K  [R0402]
R706  100K  [R0402]
R707  100K  [R0402]
R708  22K  [R0402]
R709  4.7K  [R0402]
R710  4.7K  [R0402]
R711  1K  [R0402]
R712  1K  [R0402]
U701  SY8205  [DFN4X3-12]

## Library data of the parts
C101 C103 C113 C115 C221 C402 C704 C706-C708 C711-C716 C719 = CAP_0
C102 C401 C609 C702 = CAP_NP_3
C87 C105 = CAP_NP_1
C107 = CAP_NP_1_1
C85 C86 C91 C94 C108 C109 C112 C114 = CAP_NP_0: CHIP 0.1uF 16V X7R; GenesisPartNumber: NA; Manufacturer: KEMET; PART ID: 65L0603104 12; PartNumber: C0603C104K4RAC
C110 = CAP_NP_1_2
C69-C84 C88-C90 C92 C93 C95 C99 C100 C111 C201 C209-C213 C219 C220 C226-C230 C234 C235 C237 C239 = CAP_NP_8
CN102 = INVERTER_1
H107 = HOLE-V8_1
H108 = HOLE-V8_2
H109 = HOLE-V8
H110-H115 = CON3_3
L101 = L3X3_2.2uH_1_0.5A
R101 = R0402_12K_5%
R102 = R0402_12K_5%_1
R103 R104 R110 R403 R404 R408 R709 R710 R712 = R_15
R105-R109 R307 = R_15: Package: R0603
U101 = SOT-223_1
U102 = SY8008B_1.2A
U103 = LDO_SOT-223_1117-ADJ
C202 C214 = CAP_NP_22
C203 = CAP_NP_23
C204 = CAP_NP_23_11
C205 = CAP_NP_23_8
C206 = CAP_NP_23_7
C208 = CAP_NP_23_5
C215 = CAP_NP_23_1
C216 = CAP_NP_23_13
C218 = CAP_NP_23_10
C222 = CAP_NP_23_14
C223 = CAP_NP_23_4
C224 = CAP_NP_23_6
C225 = CAP_NP_23_9
C231 = CAP_NP_23_12
C232 = CAP_NP_23_2
C233 = CAP_NP_23_3
C238 = C_5
C240 = CAP_NP_2
C278 C279 = C0402
CN201 CN407 = HEADER_1x4-2mm_180D
CN202 = CON9_1
L201 L602 = INDUCTOR_5_2
L204 L604 = INDUCTOR_5_3
L25 L205 L606 = INDUCTOR_5
L206 L603 = INDUCTOR_5_1
L207 L605 = INDUCTOR_5_4
Q201 Q303 Q402 Q703-Q705 = NPN(BEC)_1
R201-R205 R207 R213 R218 R222 R405 R406 R450 R451 R454 R455 = RESISTOR_6
R206 R208 R215 R227 R230 = RESISTOR_8: CHIP 33OHM 1/16W; A/I?: AI; PART ID: 61L0603330
R214 R224 R293 R294 = R0402
R216 = R_19_5
R217 = R0805_1
R220 = R_19_3
R225 = R0805_1_1
R226 = R_19_2
R228 = R_19_6
R229 = R_19_1
R231 = R_19
R232 = R_19_4
TP201 = TEST_POINT_1
U9 = MSD91RQN_80_1
U202 = IR
U203 U204 = M24CXX_0
Y201 = CRYSTAL_12
C301 C303 C304 = C_3: Tolerance: 20
C302 = CAP_NP_3_1: Assembly: C0603
C305 = CAP_NP_3: Assembly: C0603
CN301 = DIP-36(2*18)_0
Q301 Q302 = P_DGS_3
R304 R306 R704-R708 R711 = R_6: Package: R0603
CN401 = CON6_2_0.0mm
D401 D402 D404 D405 = BAV99_0
P401 = HDMI_J_2_VERTER_2
P402 = USB-B_1
P403 = CONNECTOR_COAX-J_0
P404 = CONNECTOR_COAX-J_0_v2
R401 = R0402_100R_5%_0
R407 R409 R632 = RESISTOR_6: Package: R0603
R414-R416 R419-R422 R452 R601-R606 R609 R611-R615 R701-R703 = R_0: Assembly: R0603
L19 = INDUCTOR_0_5
L20 = INDUCTOR_0_2
L21 = INDUCTOR_0_4
L22 = INDUCTOR_0_3
L23 = INDUCTOR_0
L24 = INDUCTOR_1_1
L26 = INDUCTOR_0_1
L27 = INDUCTOR_1_2
L87 = INDUCTOR_1
R11-R19 = R_0
T1 = TRF_ATB2012_75011_NTP: Manufacturer Part Number: ATB2012_75011
TU4 = FK1602_CAN_TUNER
TU5 = CON3_2
U7 = MxL601RF_0
U8 = SOT-223
Y5 = CRYSTAL-2pin_0
C601-C606 C608 C610 = CAP_NP_5: Assembly: C0603
C607 C718 = CAP_NP_3_2
C611-C619 = CAP_NP_5
C620 C703 = CAP_NP_3_1
CN601 CN602 = CON2
L601 = INDUCTOR_5_5
Q601 Q603 = NPN_BEC_3: MMBT3904 CHIP SOT-23-3; A/I?: SMT; PART ID: 57L 417  4
Q602 = PNP(BEC)_0
R610 = R_2
U601 = TC0177_TPA3110_0
C717 = CAP_NP_3_3
F701 = FUSE_1
F702 = FUSE
L701 = INDUCTOR_IRON_2
LED701 = 7012X_SM_2: D_Manuf: Lumex Opto/Components Inc; D_Manuf#: SML-LX1206GW-TR; F_Description: LED1206 Green LED; Manufacturer: Lumex Opto/Components Inc; Manufacturer Part Number: SML-LX1206GW-TR
P701 = DC_JACK_0
Q701 Q702 = P_DGS_2
U701 = AOZ1036_2

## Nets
+1.8V_DDR: C112.1 C113.1 C214.1 C215.1 C216.1 L207.1 R107.1 U9.28(VDDIO_CMD) U9.68(VDDIO_DATA) U103.2(OUT) U103.4(VOUT)
+1.15V_VDDC: C102.2 C103.1 C105.1 C202.1 C203.1 C204.1 C205.1 C206.1 C208.1 L101.2 R101.2 U9.27(VDDC) U9.29(VDDC) U9.58(VDDC) U9.67(DVDD_DDR_DATA) U9.75(AVDDL_DVI_VDDC)
+3.3V_Standby: C109.1 C110.1 C221.1 C222.1 C223.1 C224.1 C225.1 C238.1 L25.1 L204.1 L205.1 L206.1 R214.2 R215.1 R216.1 R224.2 R632.1 U9.11(AVDD3P3_ADC) U9.30(AVDD_MOD) U9.51(AVDD_MOD) U9.76(AVDD_MOD) U101.2(OUT) U101.4(VOUT) U203.8(VDD) U204.8(VDD)
+3.3V_TU: C71.1 C79.1 C83.1 C86.1 C87.1 L25.2 R11.1 R205.1 R206.1 R208.1 TU4.8(3.3V) U7.1(VDD_3p3) U7.11(VDD_3p3_2) U7.15(VDD_IO) U8.2(OUT) U8.4(VOUT)
+5V_HDMI: P401.18(+5V_POWER) R403.1 R404.1 R407.1 R408.1
+5V_Normal: C85.1 C114.1 C115.1 C301.1 C401.1 C402.1 P402.4(VBUS) Q301.S Q701.D R218.1 R222.1 R610.1 U8.3(IN) U103.3(IN)
+5V_Panel: C302.1 CN301.33 CN301.34 CN301.35 CN301.36 Q301.D
+5V_Standby: C101.1 C107.1 C108.1 C703.1 C707.1 C708.1 C711.1 C716.1 C718.1 CN202.1 L701.1 Q701.S R109.1 R213.1 R217.1 R227.2 R230.2 R702.1 R705.1 R712.1 U101.3(IN) U102.1(EN) U102.4(VIN) U202.3
+12V_AMP: C607.1 C608.1 C609.1 C610.1 L601.2 L602.1 R605.2 U601.16(PVDDR) U601.21(PVDDL)
+12V_AMP_A: C611.1 L602.2 U601.27(AVCC)
+12V_Normal: C303.1 C304.1 CN102.5(12V) CN102.6(12V) L601.1 Q302.S Q601.1(B) Q601.3(C) Q702.D R304.1 R609.1
+12V_Panel: C305.1 CN301.37 CN301.38 CN301.39 CN301.40 Q302.D
+12V_PWR: C704.1 C706.1 C714.1 C715.1 C717.1 F701.2 F702.2 Q702.S R701.1 R704.1 R708.1 U701.10(SVIN) U701.11(PVIN) U701.12(PVIN)
AGND: C69.2 C70.2 C71.2 C76.2 C77.2 C78.2 C79.2 C80.2 C83.2 C84.2 C85.2 C86.2 C87.2 C88.2 C89.2 C91.2 C92.2 C93.2 C94.2 C95.2 C101.2 C103.2 C105.2 C107.2 C108.2 C109.2 C110.2 C111.2 C112.2 C113.2 C114.2 C115.2 C201.2 C202.2 C203.2 C204.2 C205.2 C206.2 C208.2 C209.2 C214.2 C215.2 C216.2 C218.2 C221.2 C222.2 C223.2 C224.2 C225.2 C226.2 C231.2 C232.2 C233.2 C234.2 C235.2 C237.2 C238.2 C239.2 C240.2 C301.2 C302.2 C303.2 C305.2 C401.2 C402.2 C605.2 C606.2 C607.2 C608.2 C609.2 C610.2 C611.2 C616.2 C617.2 C618.2 C619.2 C620.2 C704.2 C706.2 C707.2 C708.2 C711.2 C712.2 C713.2 C714.2 C715.2 C716.2 C719.2 CN102.1(GND) CN102.2(GND) CN201.2 CN202.2 CN202.6 CN301.1 CN301.2 CN301.15 CN301.16 CN301.29 CN301.30 CN301.31 CN301.32 CN401.2 CN401.4 CN407.2 D401.2 D402.2 D404.2 D405.2 H107.2 H107.3 H107.4 H107.5 H107.6 H107.7 H107.8 H107.9 H108.2 H108.3 H108.4 H108.5 H108.6 H108.7 H108.8 H108.9 H109.2 H109.3 H109.4 H109.5 H109.6 H109.7 H109.8 H109.9 L22.2 L23.2 L26.2 L201.2 LED701.2(Cathode) P401.2(DATA2_SHIELD) P401.5(DATA1_SHIELD) P401.8(DATA0_SHIELD) P401.11(CLK_SHIELD) P401.17(DDC/CEC_GND) P401.20(GND1) P401.21(GND2) P401.22(GND3) P401.23(GND3) P402.1(GND) P402.5(SHELL) P402.6(SHELL) P403.1 P403.3 P403.5 P404.1 P404.3 P701.2(AC) P701.3(AC) Q201.2(EMITTER) Q303.2(EMITTER) Q402.2(EMITTER) Q603.2(E) Q703.2(EMITTER) Q704.2(EMITTER) Q705.2(EMITTER) R12.2 R102.2 R105.2 R106.2 R108.2 R202.1 R232.1 R294.2 R414.2 R415.2 R416.2 R421.2 R422.2 R450.2 R451.2 R452.2 R601.1 R602.1 R603.2 R604.1 R606.1 R613.2 R614.2 R703.2 R711.2 TU4.5(GND) TU4.10(GND) TU4.11(GND) TU4.12(GND) TU4.13(GND) TU5.2 TU5.3 TU5.4 TU5.5 U7.14(GND_DIG) U7.21(GND_XTAL) U7.24(AS) U7.25(GND) U7.26(GND) U7.27(GND) U7.28(GND) U7.29(GND) U7.30(GND) U7.31(GND) U7.32(GND) U7.33(GND) U8.1(ADJ) U9.74(GND) U9.81(E-PAD) U101.1(ADJ) U102.2(GND) U202.2 U203.4(VSS) U204.4(VSS) U601.6(AVSS) U601.9(JD_(AVSS)) U601.10(HPVSS_(AVSS)) U601.29(PVSS) U701.13(GND) Y201.3
AVDD_AU33: C233.1 L206.2 U9.14(AVDD_AU33)
AVDD_DADC: C231.1 L204.2 U9.23(AVDD3P3_DADC)
AVDD_DDR_DATA: C218.1 L207.2 U9.69(VDDIO_DRAM)
AVDD_DMPLL: C232.1 L205.2 U9.24(AVDD3P3_DMPLL)
VDD_1.8V_OUTPUT: C70.1 C76.1 C77.1 C84.1 L24.1 U7.12(VDD_1p8_2) U7.22(VDD_1p8_3)
AMP-EN: Q603.3(C) R610.2 U601.28(EN)
AMP-Lout+: C616.1 CN601.2 L603.2
AMP-Lout-: C617.1 CN601.1 L604.2
AMP-MUTE: L87.1 R615.1 R632.2
AMP-Rout+: C618.1 CN602.1 L605.2
AMP-Rout-: C619.1 CN602.2 L606.2
AUL0: C219.2 U9.16(AUL0)
AUR0: C220.2 U9.15(AUR0)
AUVAG: C228.1 C229.1 U9.17(VAG)
BIN0: C213.2 U9.6(BIN0P)
BL-ADJUST: C111.1 CN102.3(BRI_ADJ) R103.1 R105.1
BL-ON/OFF: CN102.4(BRI_ON/OFF) R104.1 R106.1
BRI_ADJ: R103.2 U9.55(PWM0)
BSTNL: C613.1 U601.19(BSTNL)
BSTNR: C615.1 U601.18(BSTNR)
BSTPL: C612.1 U601.23(BSTPL)
BSTPR: C614.1 U601.14(BSTPR)
CEC: P401.13(CEC) R401.1
CVBS0: C278.1 U9.12(CVBS0P)
CVBS_IN: CN407.1 R293.2 R452.1
CVBS_VCOM: C279.2 R294.1
DIFM: C230.2 R15.2
DIFP: C227.2 R17.2
GAIN: R605.1 R606.2 U601.24(GAIN)
GIN0: C212.2 U9.7(GIN0P)
GIN0N: C211.2 U9.8(GIN0M)
GVDD: C605.1 U601.5(GVDD) U601.13(HPVDD_(GVDD2))
HDMI-CEC: R401.2 U9.72(CEC)
HDMI-CLKN: P401.12(CLK-) U9.77(RXCN_B)
HDMI-CLKP: P401.10(CLK+) U9.78(RXCP_B)
HDMI-HPD: R408.2 R409.2 U9.73(HOTPLUG_A)
HDMI-RX0N: P401.9(DATA0-) U9.79(RX0N_B)
HDMI-RX0P: P401.7(DATA0+) U9.80(RX0P_B)
HDMI-RX1N: P401.6(DAT1A-) U9.1(RX1N_B)
HDMI-RX1P: P401.4(DATA1+) U9.2(RX1P_B)
HDMI-RX2N: P401.3(DATA2-) U9.3(RX2N_B)
HDMI-RX2P: P401.1(DATA2+) U9.4(RX2P_B)
HDMI-SCL: R405.2 U9.71(DDCDA_CL)
HDMI-SDA: R406.2 U9.70(DDCDA_DA)
HDMI_HPD: P401.19(HOT_PLUG) Q402.3(COLLECTOR) R407.2
HDMI_SCL: D401.1 P401.15(SCL) R403.2 R405.1
HDMI_SDA: D402.1 P401.16(SDA) R404.2 R406.1
IF-AGC-T: C95.1 R19.2 TU4.1(IF_AGC) U7.6(AGC_1)
IF-IN+: C81.2 C94.1 R17.1 TU4.2(DIFP)
IF-IN-: C82.2 C91.1 R15.1 TU4.3(DIFN)
IF_AGC: C226.1 R19.1 R207.2
IFAGC: R205.2 R207.1 U9.20(IFAGC)
INNL: C602.1 U601.2(INNL)
INNR: C603.1 U601.3(INNR)
INPL: C601.1 U601.1(INPL)
INPR: C604.1 U601.4(INPR)
IR-IN: CN202.3 R217.2 R225.2 U202.1
IRIN: C237.1 R225.1 U9.57(IRIN)
KEY0-in: R231.1 U9.65(SAR0)
LED-R: CN202.4 Q201.3(COLLECTOR) R213.2 R218.2
Mute: Q602.3(COLLECTOR) R612.1 R614.1
PANEL-ON: Q303.3(COLLECTOR) R304.2 R306.2
PANEL_ON/OFF: R232.2 R307.1 U9.56(PWM1)
PWR-ON/OFF: R109.2 R110.2 U9.54(GPIO0)
RF: L20.2 TU5.1
RIN0: C210.2 U9.9(RIN0P)
RXE0+: CN301.17 U9.41(G_ODD[0]/LVA0+)
RXE0-: CN301.18 U9.42(G_ODD[1]/LVA0-)
RXE1+: CN301.19 U9.39(B_ODD[6]/LVA1+)
RXE1-: CN301.20 U9.40(B_ODD[7]/LVA1-)
RXE2+: CN301.21 U9.37(B_ODD[4]/LVA2+)
RXE2-: CN301.22 U9.38(B_ODD[5]/LVA2-)
RXE3+: CN301.25 U9.33(B_ODD[0]/LVA3+)
RXE3-: CN301.26 U9.34(B_ODD[1]/LVA3-)
RXEC+: CN301.9 CN301.23 U9.35(B_ODD[2]/LVACLK+)
RXEC-: CN301.10 CN301.24 U9.36(B_ODD[3]/LVACLK-)
RXO0+: CN301.3 U9.49(R_ODD[0]/LVB0+)
RXO0-: CN301.4 U9.50(R_ODD[1]/LVB0-)
RXO1+: CN301.5 U9.47(G_ODD[6]/LVB1+)
RXO1-: CN301.6 U9.48(G_ODD[7]/LVB1-)
RXO2+: CN301.7 U9.45(G_ODD[4]/LVB2+)
RXO2-: CN301.8 U9.46(G_ODD[5]/LVB2-)
RXO3+: CN301.11 U9.43(G_ODD[2]/LVB3+)
RXO3-: CN301.12 U9.44(G_ODD[3]/LVB3-)
SC_AUL: C219.1 R451.1 R454.2
SC_AUR: C220.1 R450.1 R455.2
SCL-T: C93.1 R16.2 TU4.7(SCL) U7.16(SCL)
SDA-T: C92.1 R14.2 TU4.6(SDA) U7.17(SDA)
SPI-CS1N: R214.1 U9.62(SPI_CZ) U203.1(CE#) U204.1(CE#)
SPI-HOLD: R224.1 U203.7(HOLD#) U204.7(HOLD#)
SPI-SCK: U9.60(SPI_CLK) U203.6(SCK) U204.6(SCK)
SPI-SDI: U9.59(SPI_DI) U203.5(SI) U204.5(SI)
SPI-SDO: U9.61(SPI_DO) U203.2(SO) U204.2(SO)
SPI-WP: R215.2 U203.3(WP#) U204.3(WP#)
SPK_L: C209.1 C601.2 U9.18(EAR_PHONE_OUTL)
SPK_R: C201.1 C604.2 U9.19(EAR_PHONE_OUTR)
STANDBY: Q703.3(COLLECTOR) R110.1 R709.1 R710.1
T_SCL: R16.1 R206.2 U9.53(GPIO1)
T_SDA: R14.1 R208.2 U9.52(GPIO2)
UART-RX: R226.2 R227.1 U9.64(DDCA_CK)
UART-TX: R229.2 R230.1 U9.63(DDCA_DA)
USB1_D+: D404.1 P402.2(D+) U9.32(DP_P0)
USB1_D-: D405.1 P402.3(D-) U9.31(DM_P0)
VBL_CTRL: R104.2 U9.66(SAR1)
VCOM0: C279.1 U9.13(VCOM)
VGA_HSYNC: R420.2 U9.5(HSYNC0)
VGA_VSYNC: R419.2 U9.10(VSYNC0)
VIFM: C230.1 U9.21(VIFP)
VIFP: C227.1 U9.22(VIFM)
VOUTNL: C613.2 L604.1 U601.20(VOUTNL)
VOUTNR: C615.2 L606.1 U601.17(VOUTNR)
VOUTPL: C612.2 L603.1 U601.22(VOUTPL)
VOUTPR: C614.2 L605.1 U601.15(VOUTPR)
XTAL: C235.1 R18.2 R220.1
XTALI: C239.1 R228.1 U9.25(XIN) Y201.1
XTALO: C234.1 R220.2 R228.2 U9.26(XOUT) Y201.2
YPBPR_AUL: CN407.3 P404.2 R454.1
YPBPR_AUR: CN407.4 P404.4 R455.1
YPBPR_PB: CN401.5 P403.4 R204.1 R415.1
YPBPR_PR: CN401.1 P403.6 R201.1 R414.1
YPBPR_Y: CN401.3 P403.2 R203.1 R416.1
N205056: C72.1 L19.1 T1.2(OUT1)
N205060: C72.2 U7.2(LNA_INP)
N205068: C75.1 C99.2 L21.1 R13.1 T1.4(IN2)
N205080: C78.1 L24.2 U7.4(VDD_1p8_1)
N205254: C81.1 U7.9(IF_OUTN_1)
N205258: C82.1 U7.10(IF_OUTP_1)
N205286: C80.1 U7.13(VDD_1p2)
N205340: C73.2 U7.3(LNA_INN)
N205376: C74.1 L20.1 L22.1
N205396: C69.1 R11.2 U7.23(RESET_N)
N205494: C74.2 C99.1 C100.1 L21.2
N205660: L19.2 R12.1 R13.2 T1.3(OUT2)
N205722: C73.1 C75.2 L23.1 T1.1(IN1)
N348192: F701.1 F702.1 P701.1(AC)
N351922: C719.1 Q703.1(BASE) R708.2 R711.1
N352631: C717.2 Q702.G R706.1
N1683944: C702.1 L701.2 U701.2(OUT) U701.3(OUT) U701.4(OUT)
N1684577: C703.2 R702.2 R703.1 U701.7(FB)
N4856806: C718.2 Q701.G R707.1
N4856984: Q705.1(BASE) R710.2
N4857034: Q705.3(COLLECTOR) R705.2 R707.2
N4888870: R107.2 R108.1 U103.1(ADJ)
N4970871: C102.1 R101.1 R102.1 U102.5(FB)
N4970875: L101.1 U102.3(SW)
N5806522: Q402.1(BASE) R409.1
N5855059: C240.1 CN202.8 R216.2 R231.2
N5855199: Q201.1(BASE) R222.2
N5944085: C228.2 C229.2 L201.1
N5953643: CN201.4 R229.1
N5953647: CN201.3 R226.1
N6137154: U7.20(XTAL_P) Y5.2
N6185092: L27.1 U7.19(XTAL_N) Y5.1
N6228574: CN401.6 R419.1 R422.1
N6238530: CN401.7 R420.1 R421.1
N6804778: C278.2 R293.1
N6941311: C702.2 U701.1(BS)
N6991285: C606.1 R604.2 U601.25(PLIMIT)
N6991989: R603.1 U601.26(SR_CTRL)
N6992251: C602.2 R601.2
N6992309: C603.2 R602.2
N7047058: C88.1 L87.2 U7.7(IF_OUTN_2/GPO_1)
N7087549: TP201.1(\) U9.82(TEST)
N7131495: Q602.1(BASE) R609.2
N7144031: C89.1 C90.2 R18.1
N7144071: C90.1 L27.2
N7156759: C100.2 L26.1
N130405484: Q602.2(EMITTER) R611.2
N130405496: Q603.1(B) R612.2 R615.2
N130405517: C620.1 Q601.2(E) R611.1 R613.1
N136219735: Q704.1(BASE) R709.2
N136219789: LED701.1(Anode) R712.2
N136220055: Q704.3(COLLECTOR) R704.2 R706.2
N136220087: C712.1 U701.9(VCC)
N136759383: C713.1 U701.8(SS)
N136887516: R701.2 U701.5(E~{N})
N138459638: C211.1 R202.2
N138459640: C213.1 R204.2
N138459642: C212.1 R203.2
N138459644: C210.1 R201.2
N159442367: C304.2 Q301.G Q302.G R306.1
N159442373: Q303.1(BASE) R307.2

Not connected (* = marked no-connect by the designer): CN201 1*; CN202 5* 7*; CN301 13* 14* 27* 28*; H107 1*; H108 1*; H109 1*; H110 1*; H111 1*; H112 1*; H113 1*; H114 1*; H115 1*; P401 14(NC)*; TU4 4(CLK_OUT)* 9(ANT_DC)*; U7 5(AGC_2/GPO3)* 8(IF_OUTP_2/GPO_2)* 18(CLK_OUT)*; U601 7(HPL_(NC))* 8(HPR_(NC))* 11(CN_(NC))* 12(CP_(NC))*; U701 6(PG)*

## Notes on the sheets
sheet 1
- HDMI
- Audio
- 靠近mstar IC
- CORE Power&DVDD_DDR
- CVBS
- YPbPr
- DDR_POWER
- Audio Line IN
- 靠近mstar IC
- Normal Power 3.3V
- Tuner
- Close to MST IC
  with width trace
- USB
- Config
- 50mA,15mil
- 50mA,15mil
- 50mA,15mil
- PWM0
- PWM1
- {PWM1,PWM0}
     0,  0  :Boot from SPI
     0,  1  :Boot from SPI
     1,  0  :Boot from SPI
     1,  1  :Not Boot from SPI
- IR&KEY
- Flash
- Crystal
- C1
- C2
- NOTE:晶体频偏需要小于30PPM
- C1=C2=2*CL-5
- UART
- 软件必须要做写保护
- 仿真使用，客户可以删除
sheet 2
- MXL661
- Tuner Module Optional
- SI TUNER
- Part Num
- BALUN
- NO BALUN
- L19
- NC
- 18nH
- R12
- 0R
- NC
- R13
- NC
- 0R
- L21
- L23
- 0R
- 560nH
- 18nH
- 8.2nH
- C75
- NC
- 5.6pF
- Part2
- Part1
- TUNER屏蔽罩
- Part3
- For S11 test
- Part4
- 75 ohm Line
- Part6
- Part5
- I2C Addr: 0xC0
- TUNER POWER
- CB Notch Filter,主要针对外销，欧洲等市场
- 220mA
- AGC RC Filter &I2C
- DIF IN&OUT
sheet 3
- Connector
- VDDC Power
- +3.3V_Standby
- Note：能提供最大平均电流1A。此路需要550mA
- R1
- 靠近DC-DC
- R2
- 靠近DC-DC
- Vout=0.6V*(1+R1/R2)
- +1.8V_DDR
- Control
- Vout=1.25*(1+R2/R1)
- R1
- R2
- H :Power on
  L :Power off
- TP & MARK
sheet 4
- +5V_Standby
- Note：能提供最大电流5A。
- R1
- R2
- Vout=0.6V*(1+R1/R2)
- +12V_Normal
- +5V_Normal
- Protect
- 20V-15V OFF; 12V ON
- Indicate
sheet 5
- 使用磁珠为考虑EMI，如果EMI没有问题，可以用OR
- MUTE CONTROL
- Net
- Note: De-POP电路的电源选择，请选择
  掉电最快的一组，以满足AC OFF时Mute功能。
- H :Normal
  L :Mute
- L :Normal
  H :Mute
sheet 6
- LVDS
- SZ LVDS Connector
- Power for panel
- H :Power on
  L :Power off
sheet 7
- Ver
- Date
- change list
- V1.0.0
- 2015.09.17
- Initial
- V1.0.1
- 2015.09.25
- 增加L207，隔开DDR电源
- V1.0.2
- 2015.09.30
- Pin68,Pin69网络对调
- V2.0.0
- 2016.05.31
- U9脚位新封装更改
- V2.0.0
- 2016.05.31
- 增加AV_IN部分电路
- V2.0.0
- 2016.05.31
- 功放模块由9010更改为9116
- V2.0.0
- 2016.05.31
- AMP_MUTE与Panel_on/off复用，增加反相电路。
- V2.0.1
- 2016.06.01
- AMP_MUTE修改为从TUNER的GPIO上取
- V2.0.1
- 2016.06.01
- AMP_MUTE网络增加LC电路。
- V2.0.1
- 2016.06.07
- C616,C617,C618,C619由0.22uF改为0.1nF
- V2.0.1
- 2016.06.07
- L201由FB/120R改为FB/1K
- V2.0.2
- 2016.06.17
- R107由NC改为1K，R108由0R改为470R
- V2.0.2
- 2016.06.24
- 晶振复用网络接线反，电路修改。删除R20，增加L27，C88，C89，R18。删除R221
sheet 8
- HDMI
- USB
- USB2.0 Power
- Note:电容靠近USB端子,提供usb读写稳定性
- YPbPr
- AUDIO IN
- VGA
- AV IN
